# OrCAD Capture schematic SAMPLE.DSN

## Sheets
1 PAGE1: size C; title: Sample Design; rev: A; company: EMA Design Automation; note: 1234567890; note: 225 Tech Park Dr.; note: Rochester, NY 14623
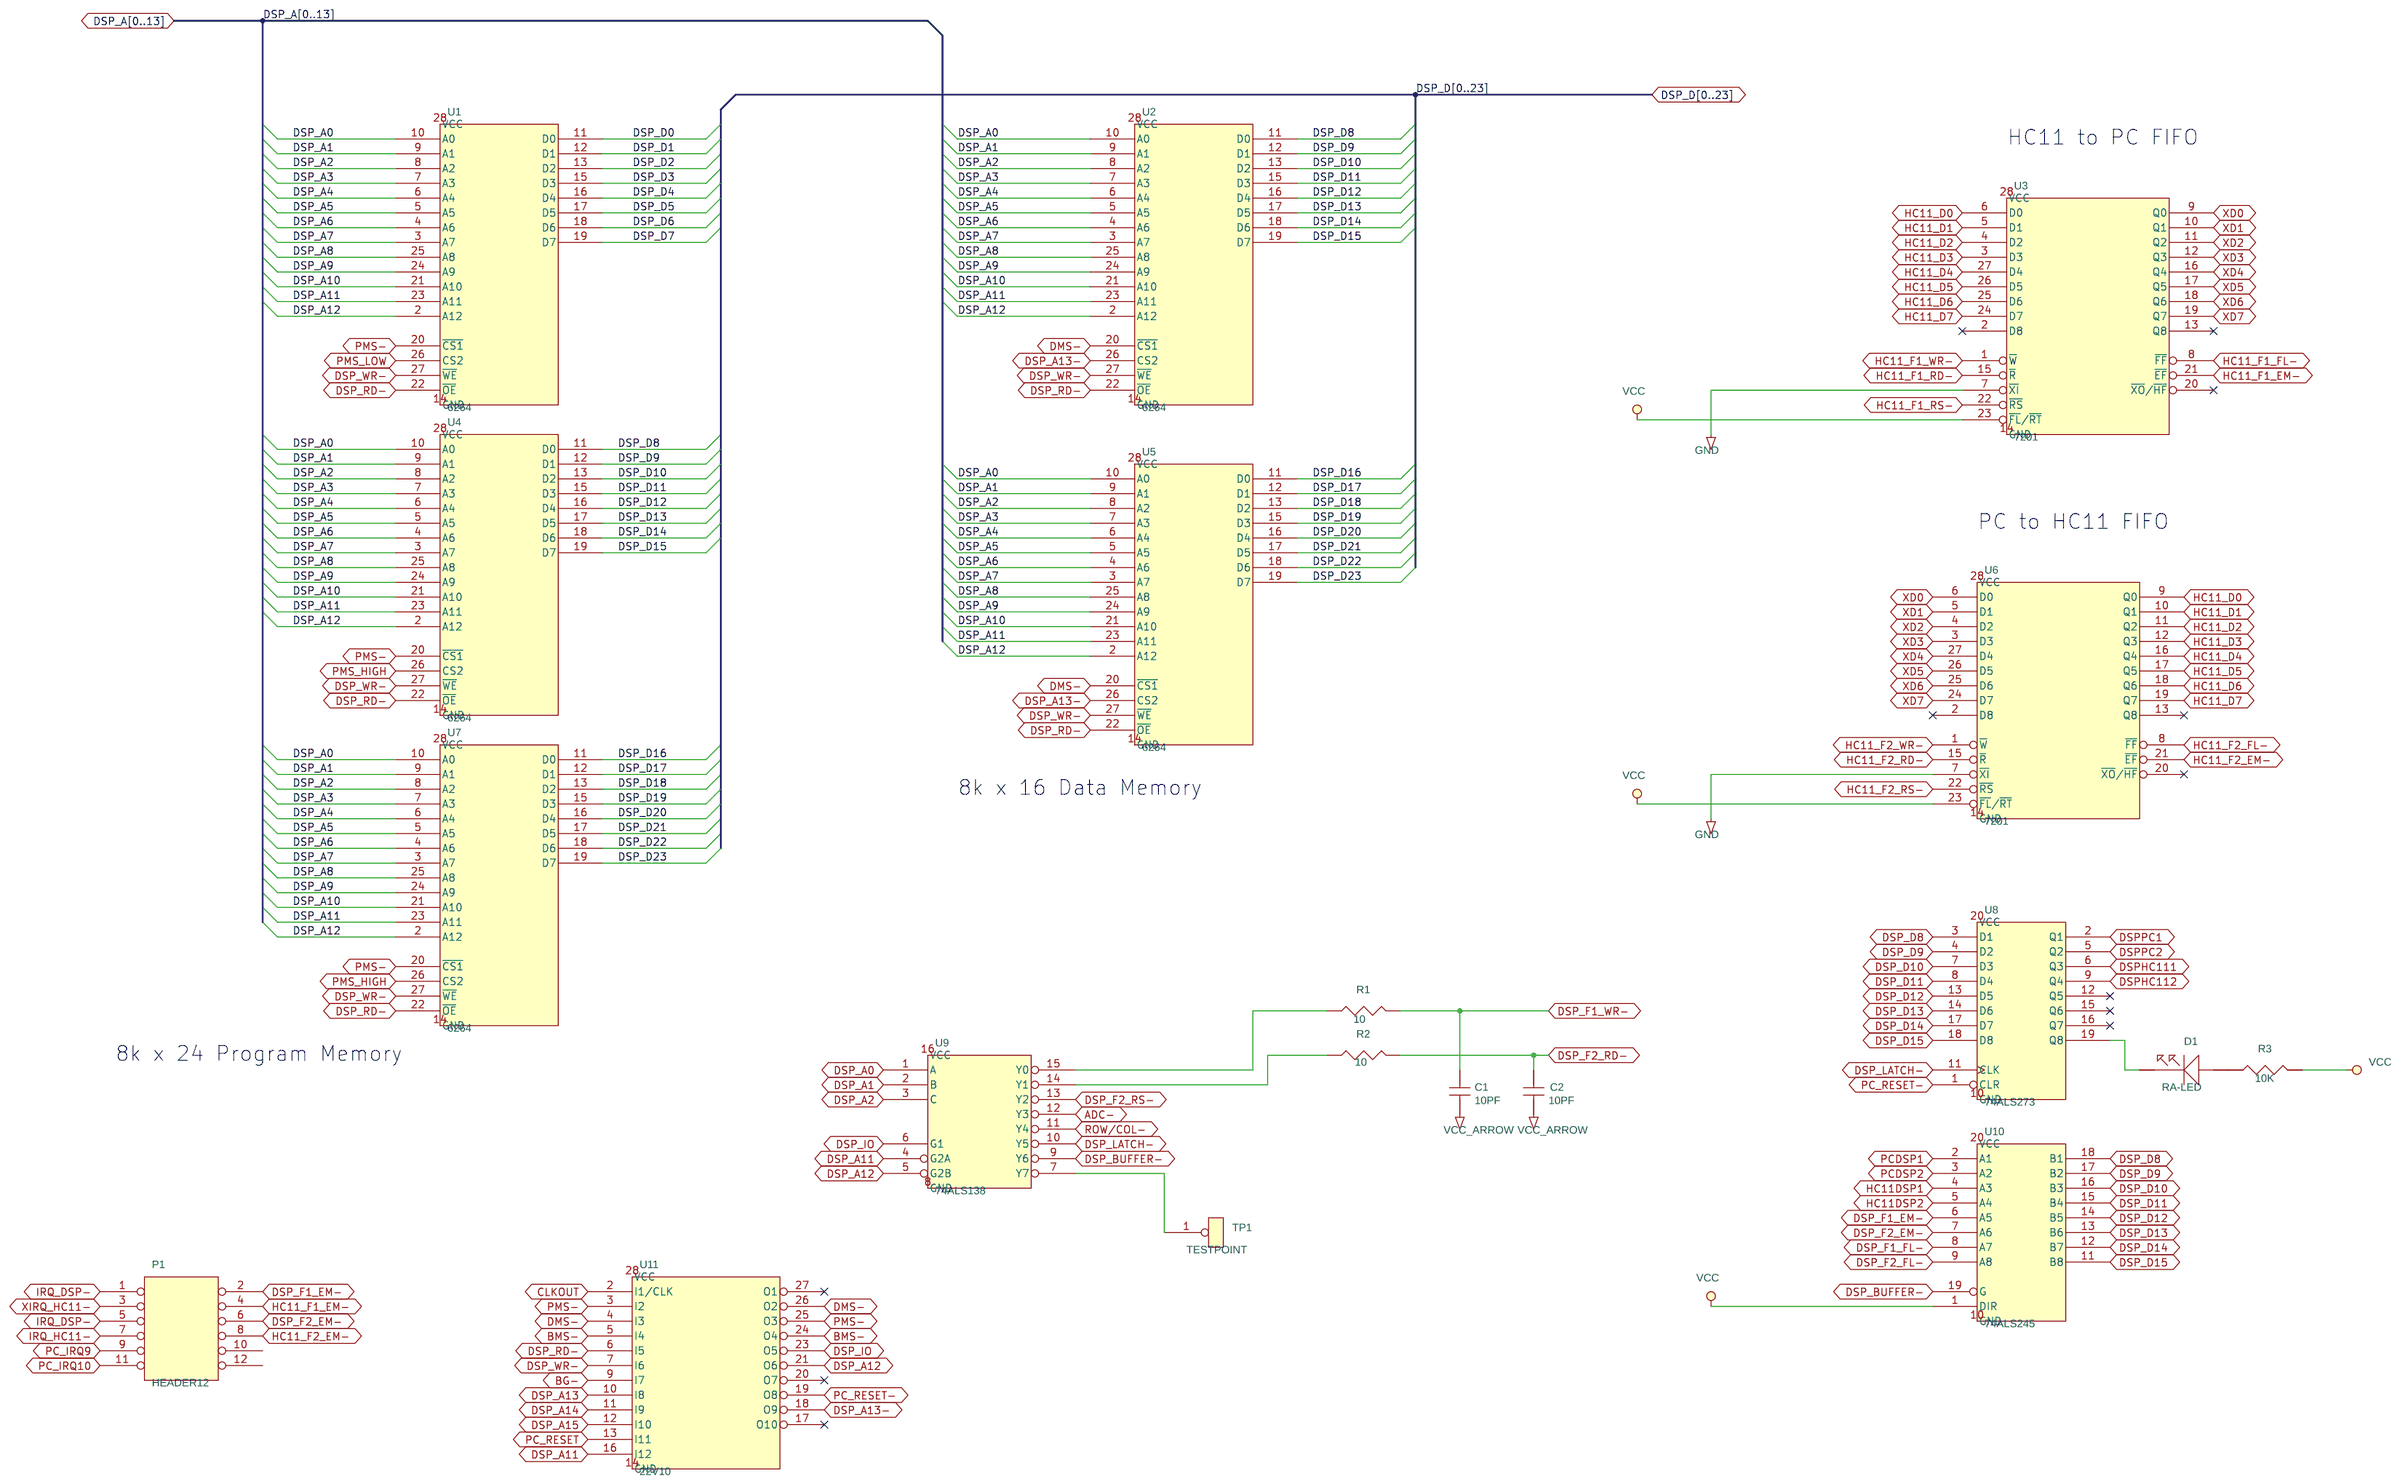
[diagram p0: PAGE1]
2 PAGE2: size C
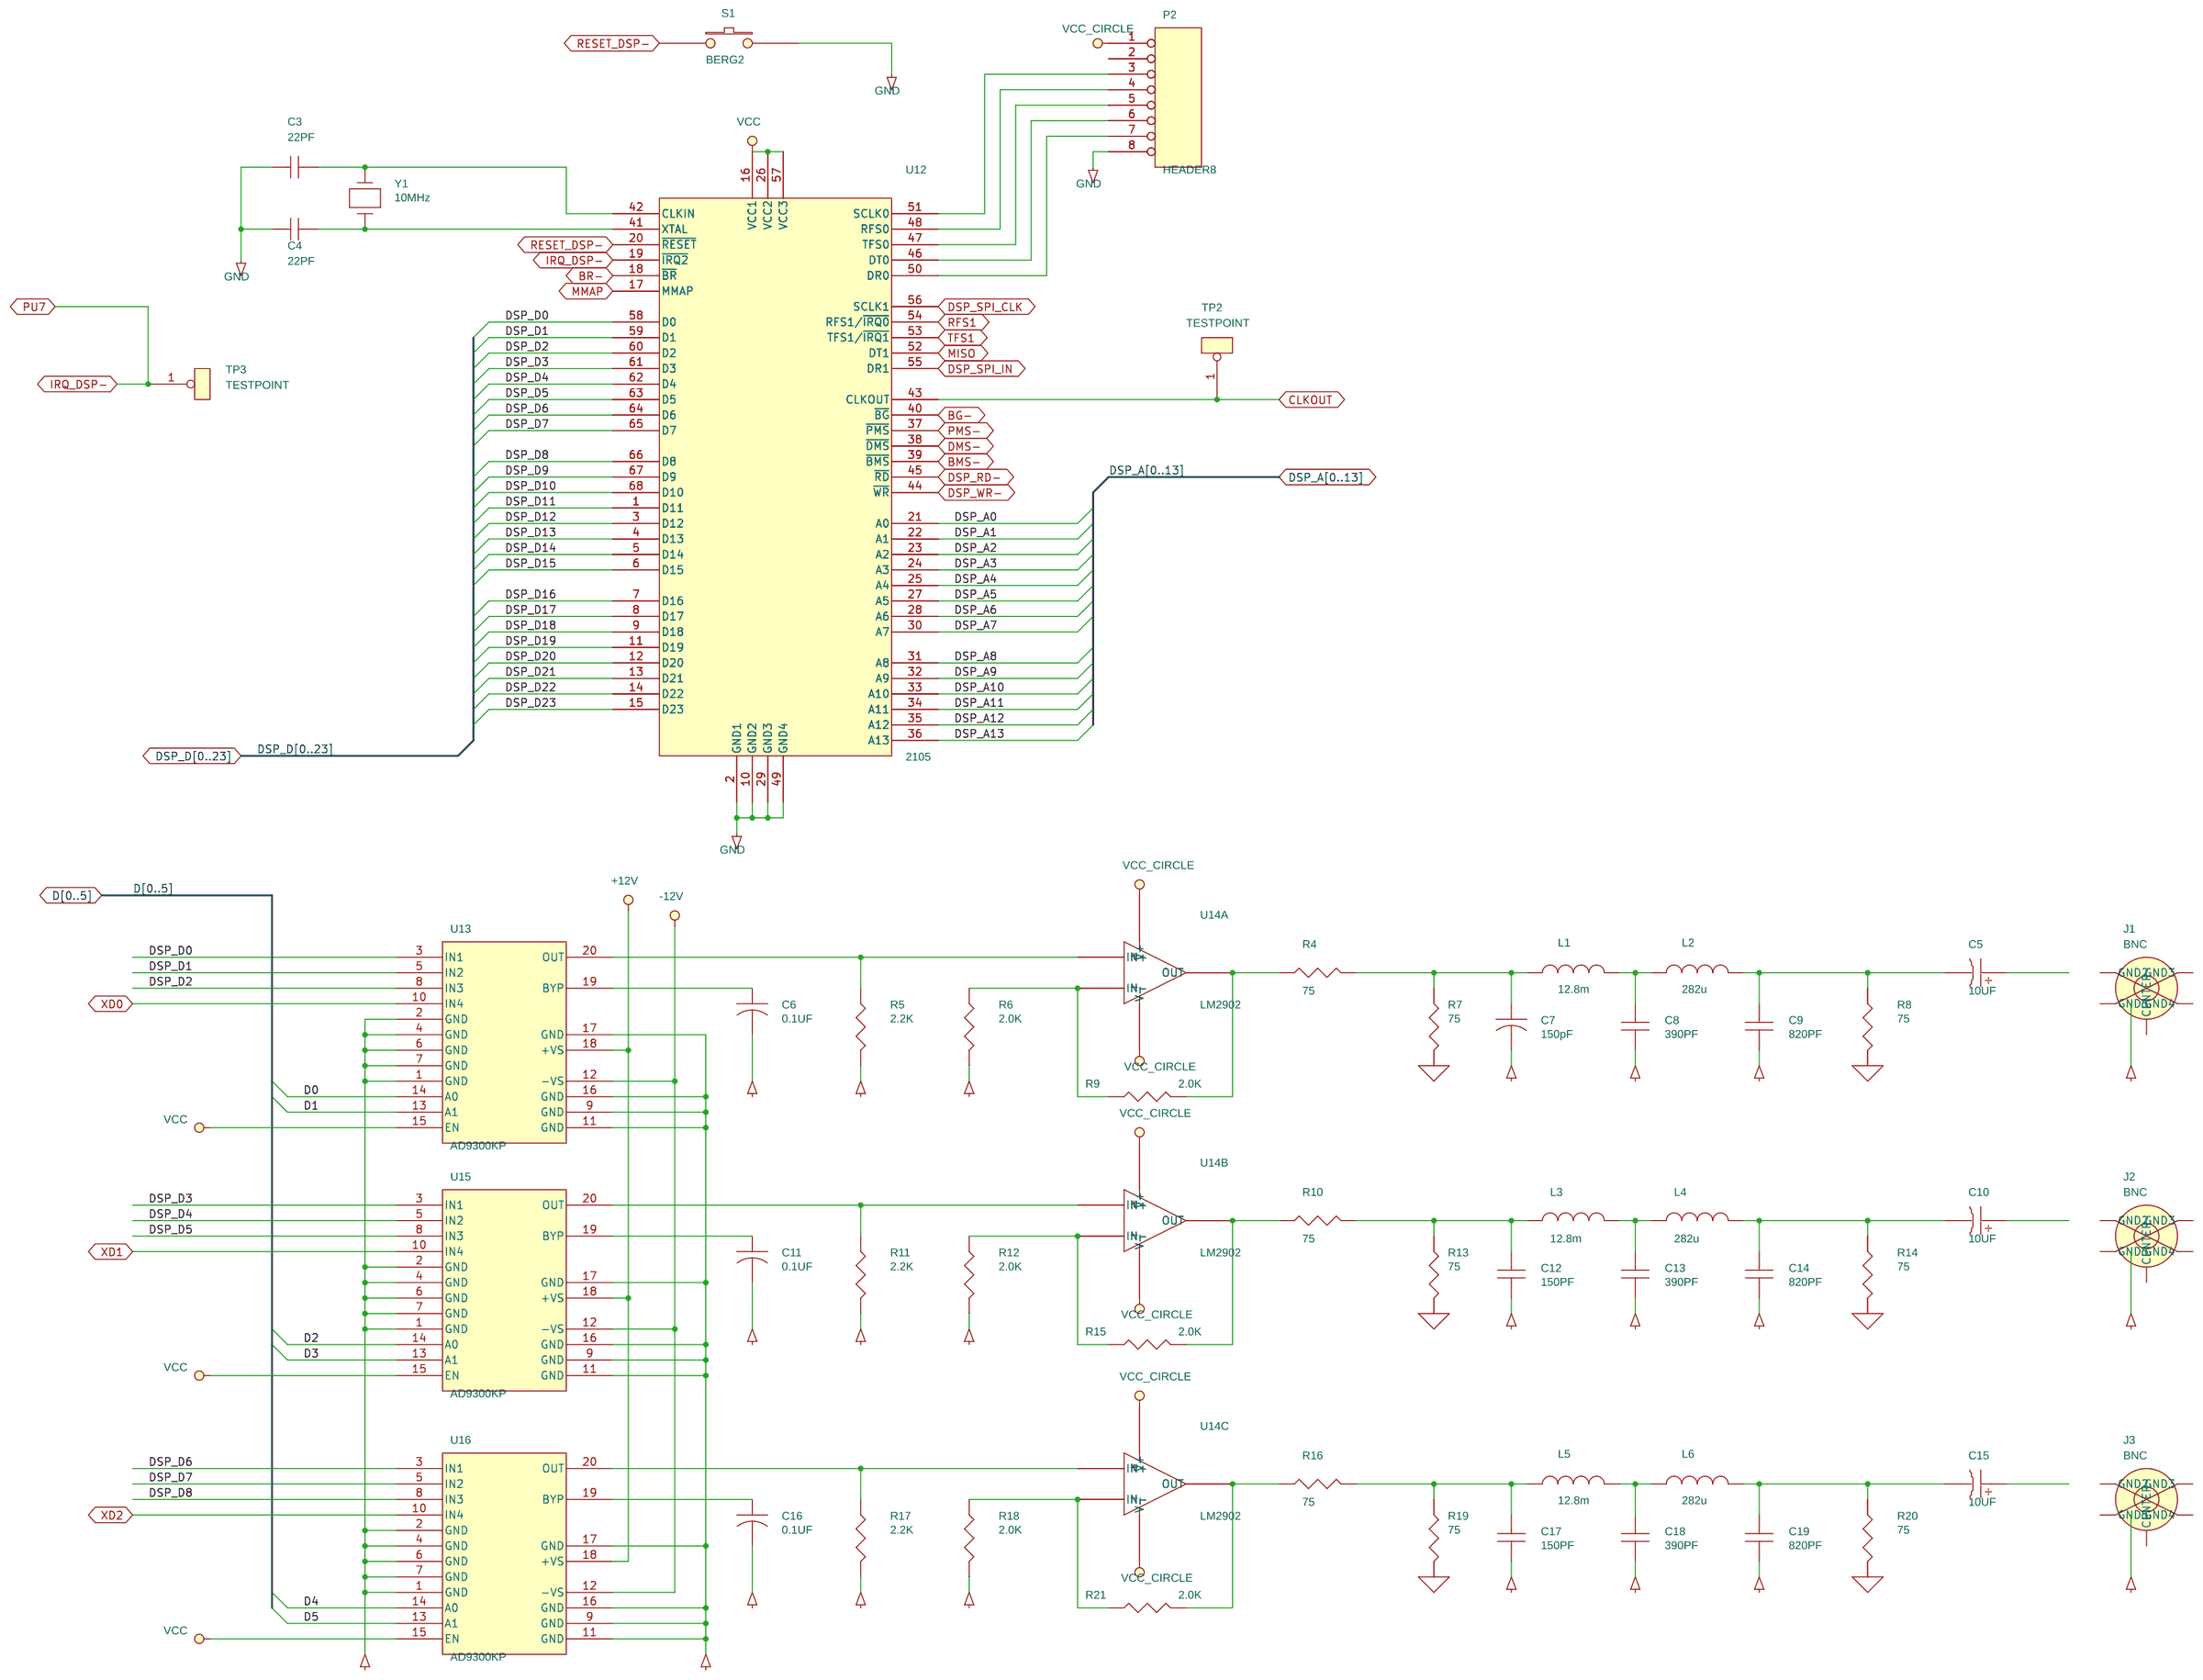
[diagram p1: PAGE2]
3 PAGE3: size C
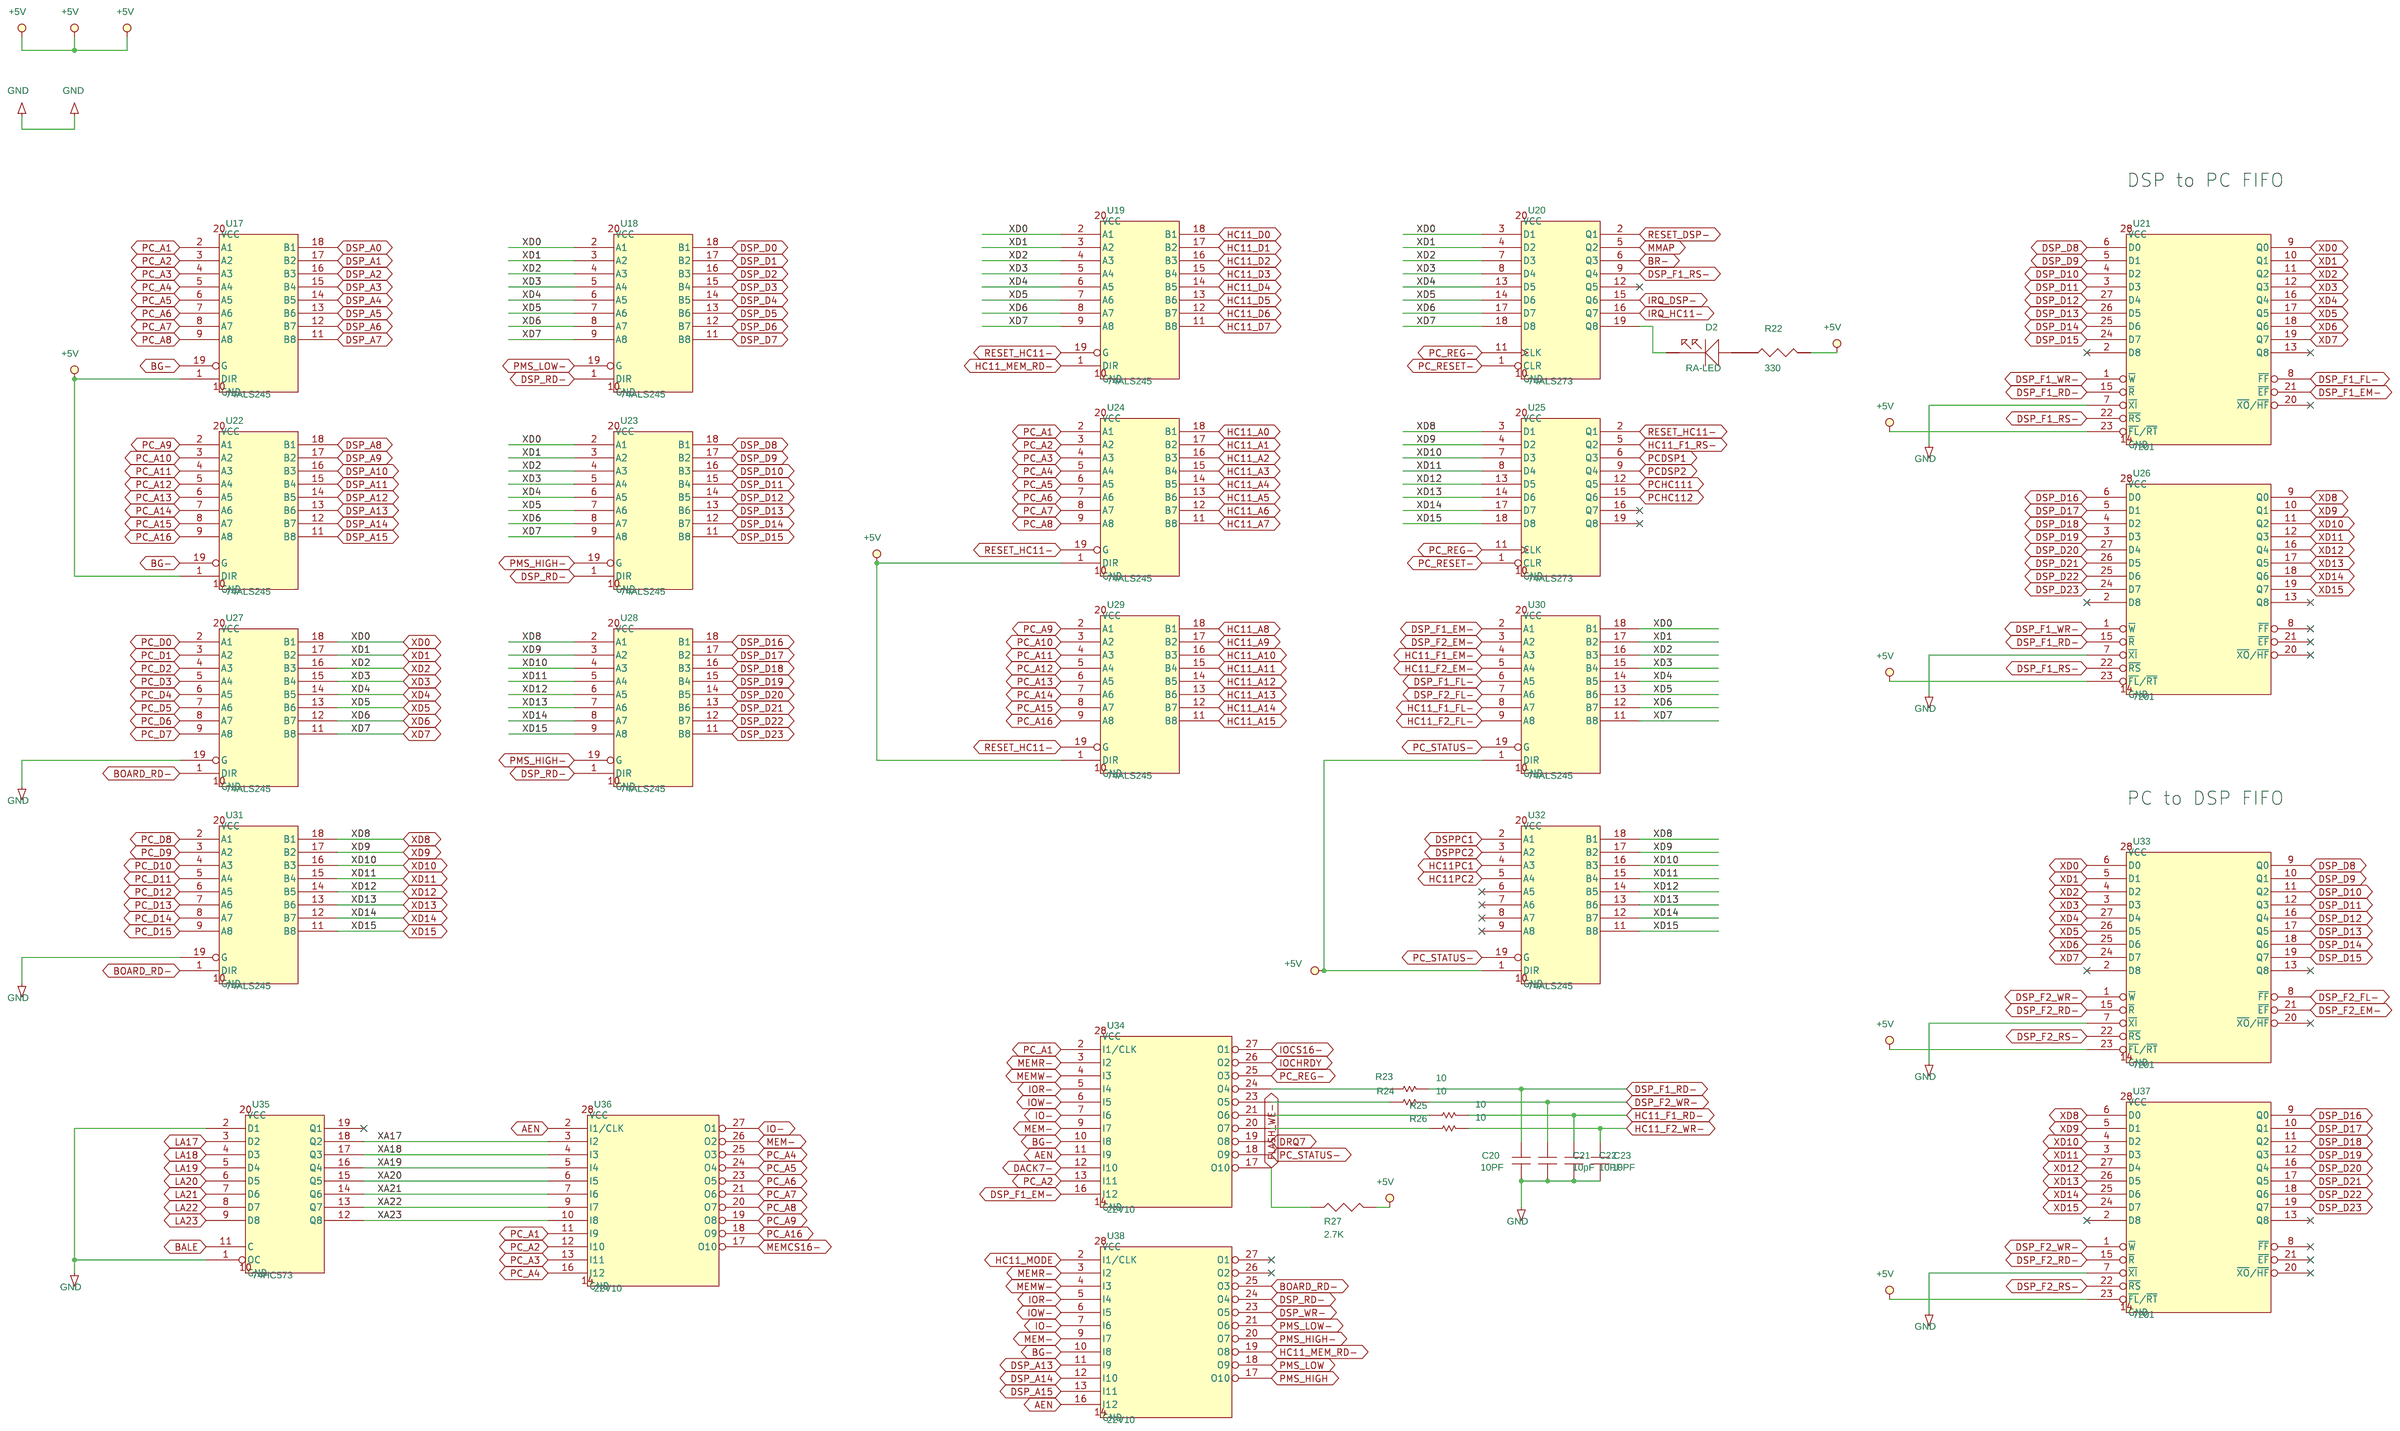
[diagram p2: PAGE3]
4 PAGE4: size C
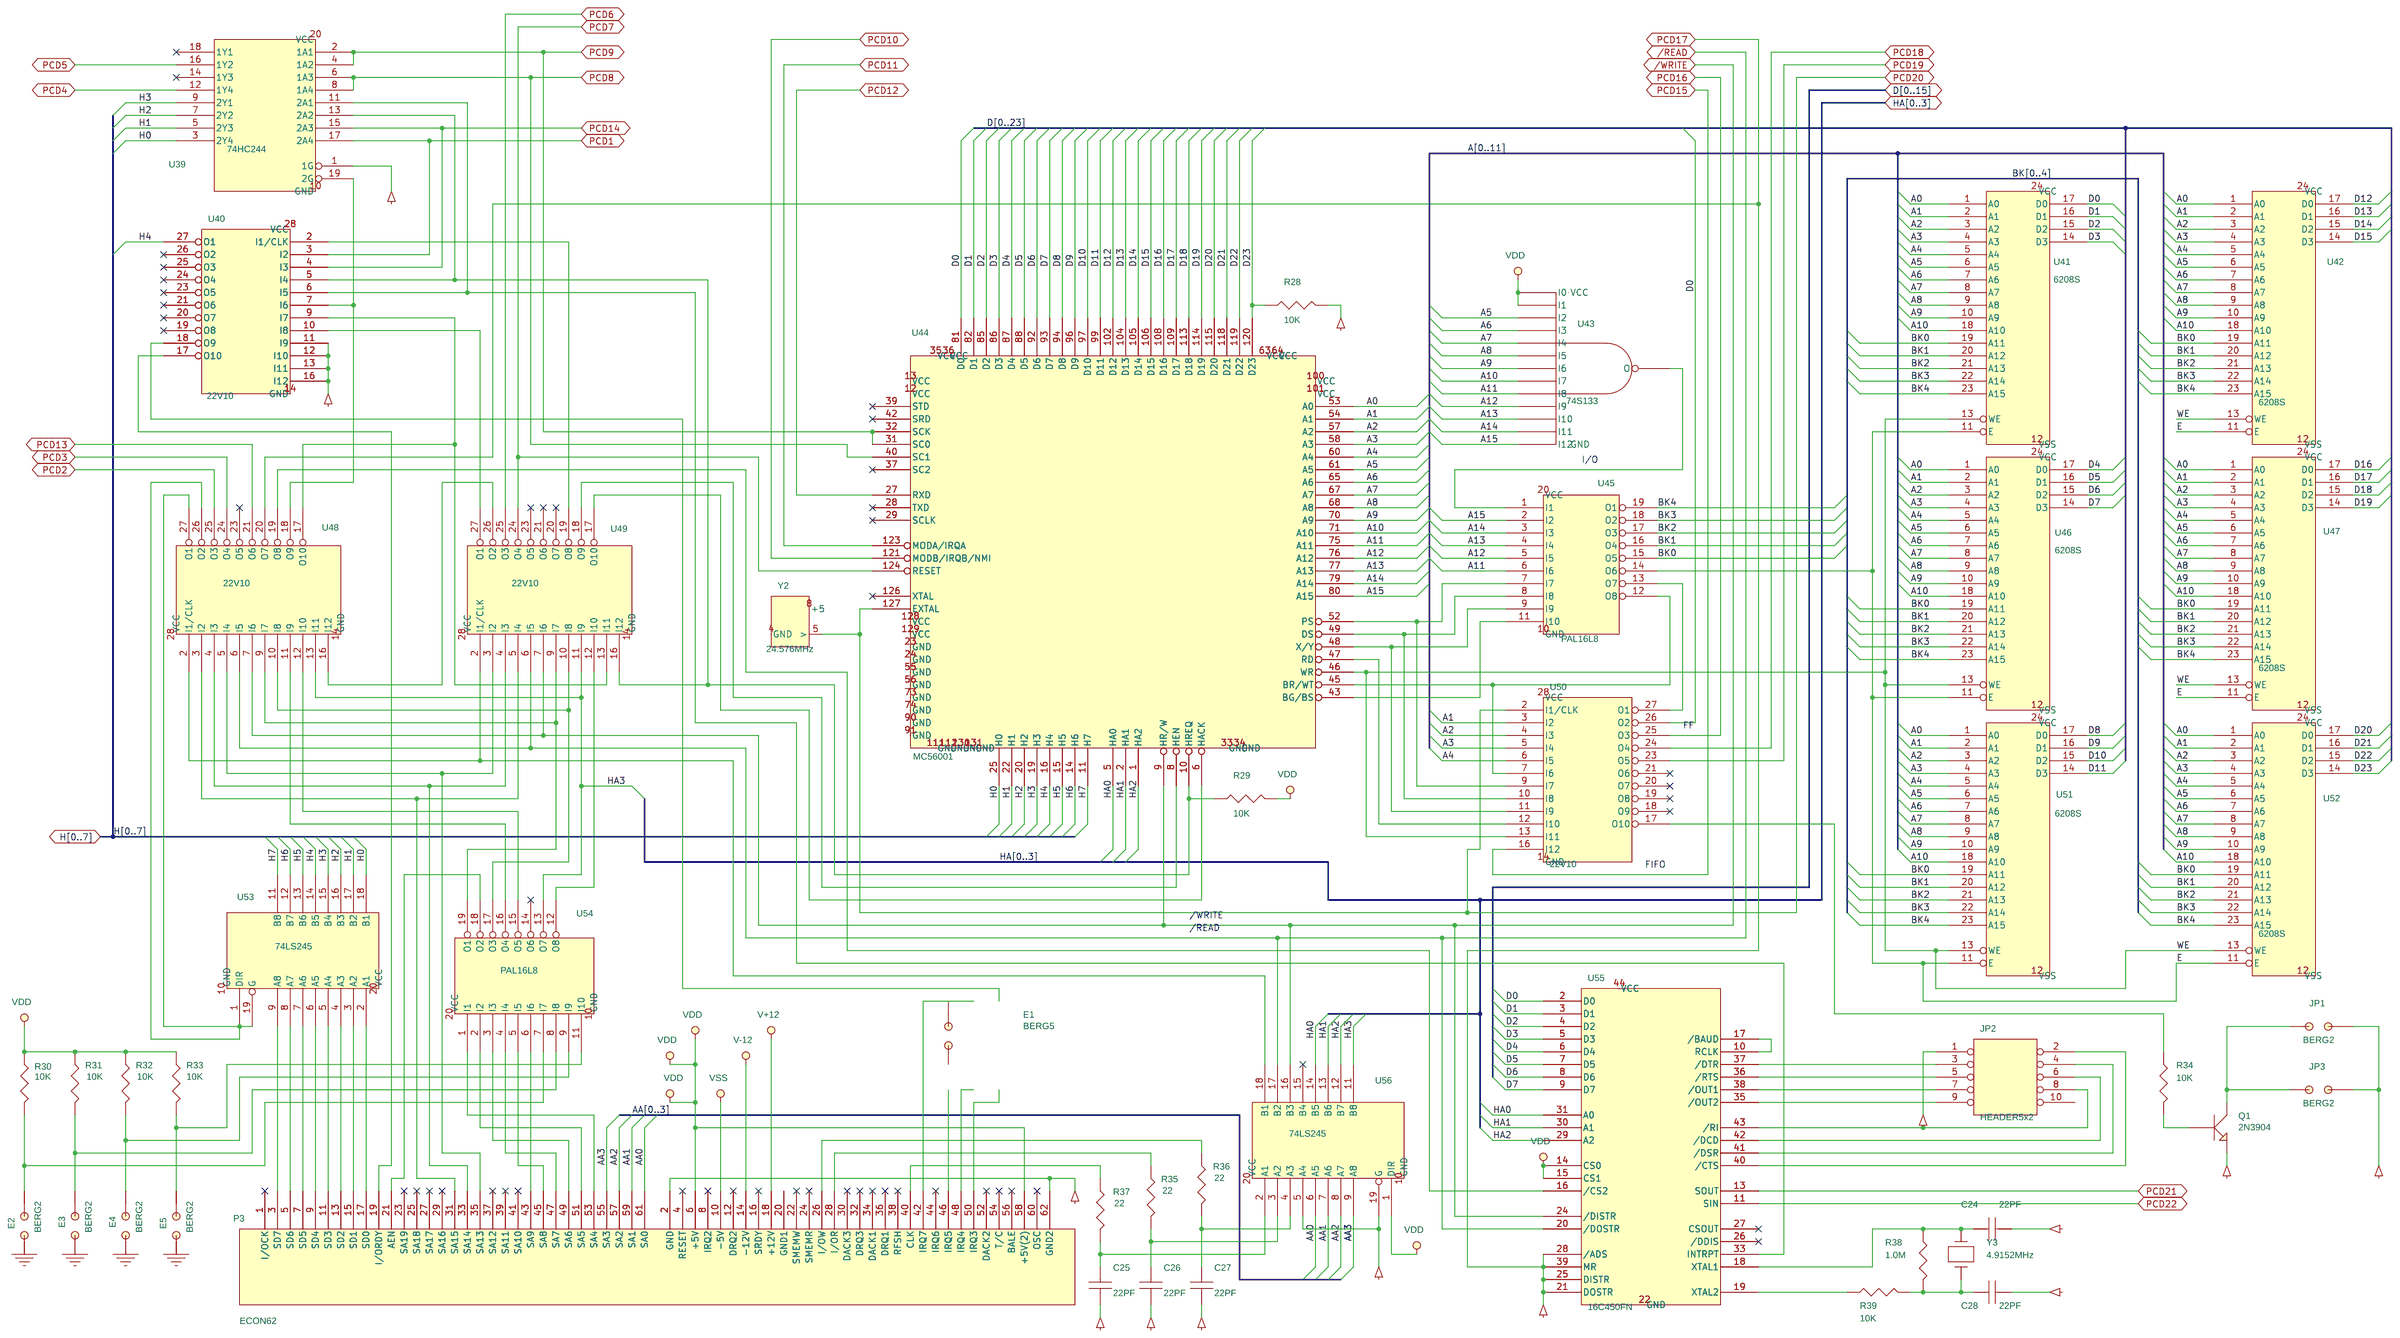
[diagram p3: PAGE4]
5 PAGE5: size C; note: Rochester, NY
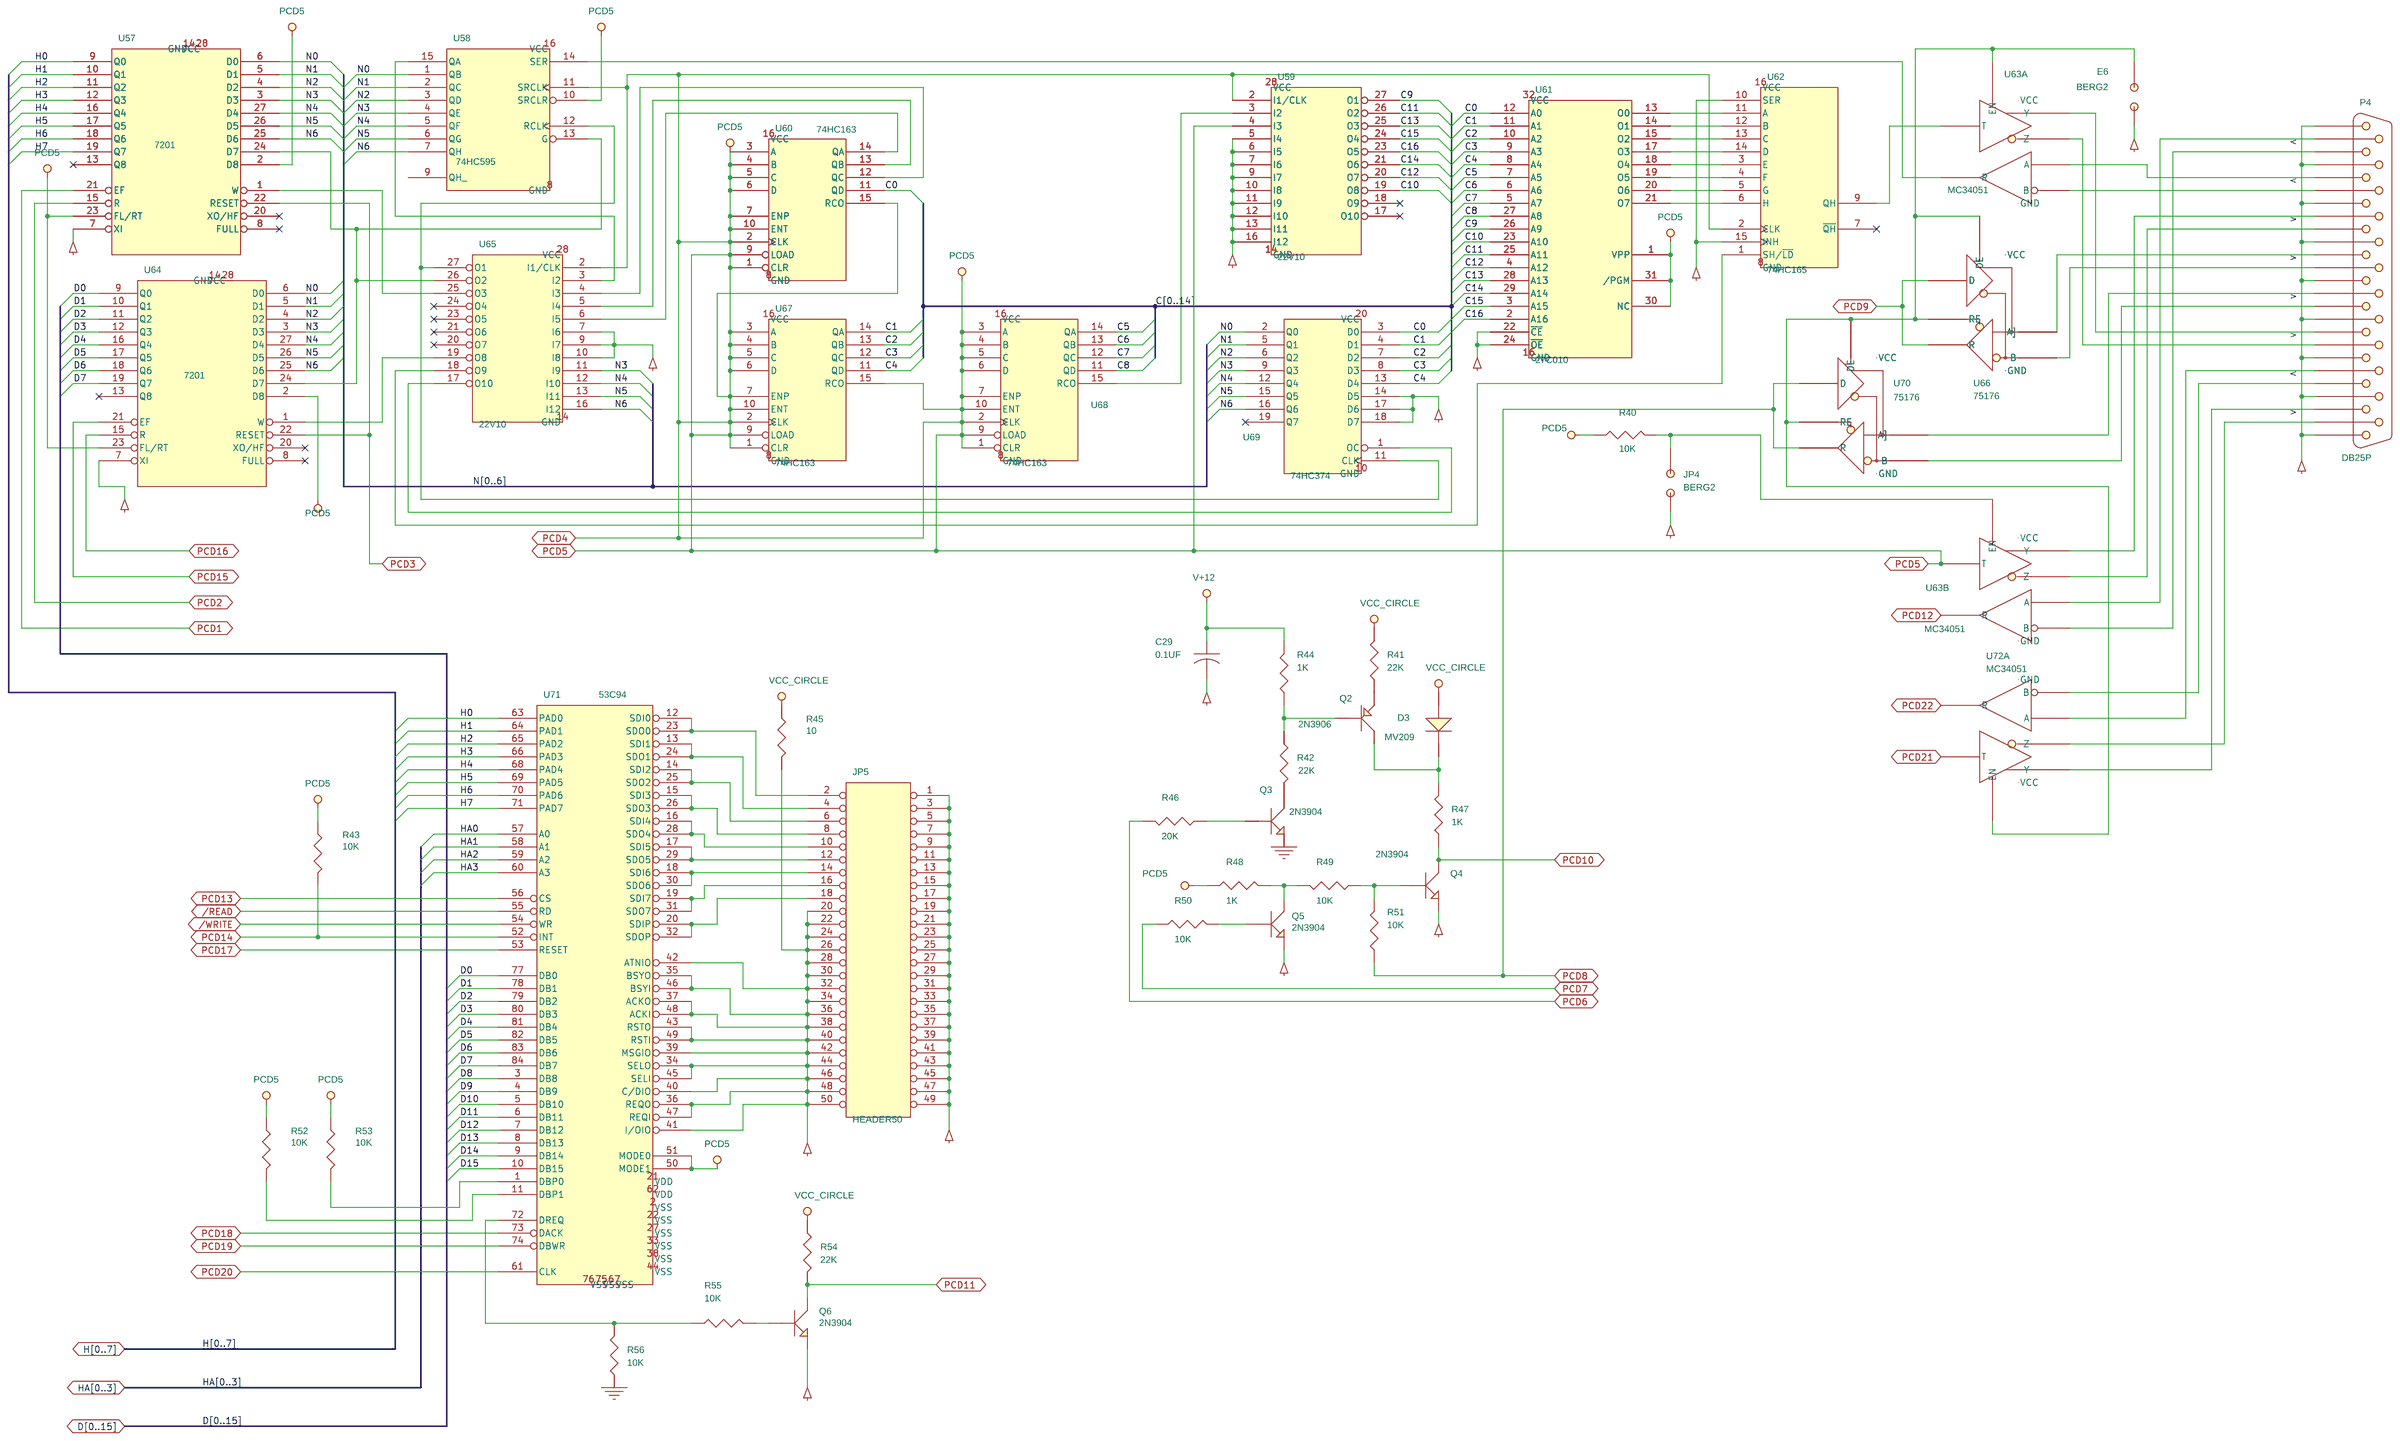
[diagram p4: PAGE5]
6 PAGE6: size C; note: Rochester, NY
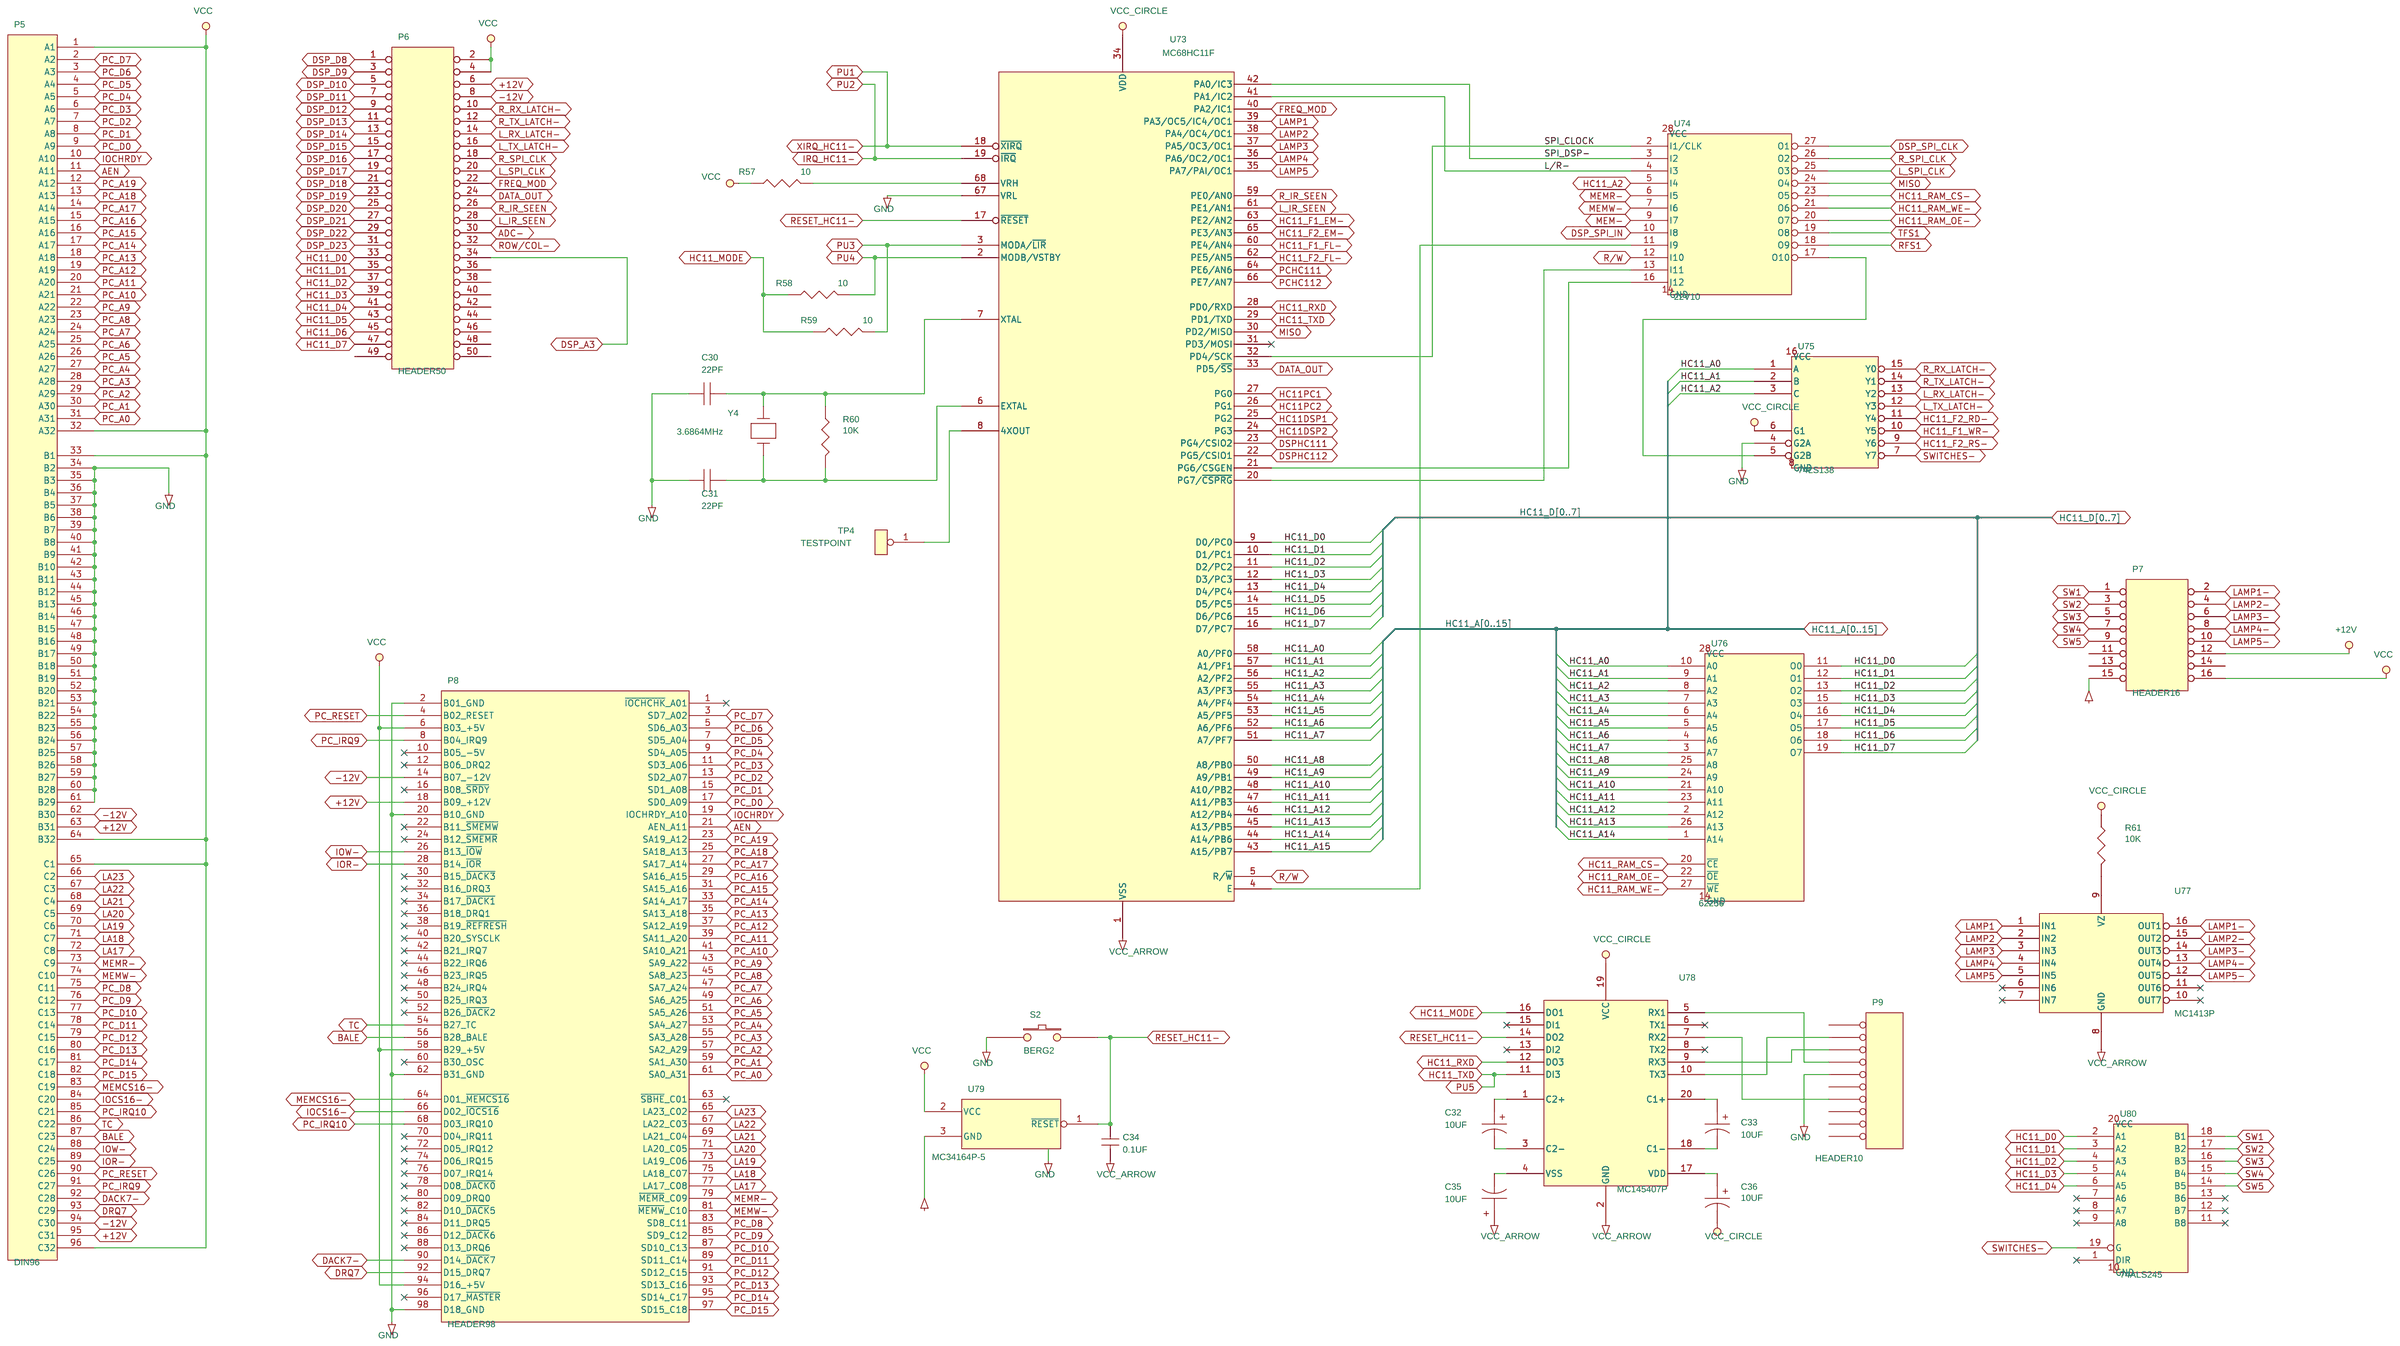
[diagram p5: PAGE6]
7 PAGE7: size B; note: Rochester, NY
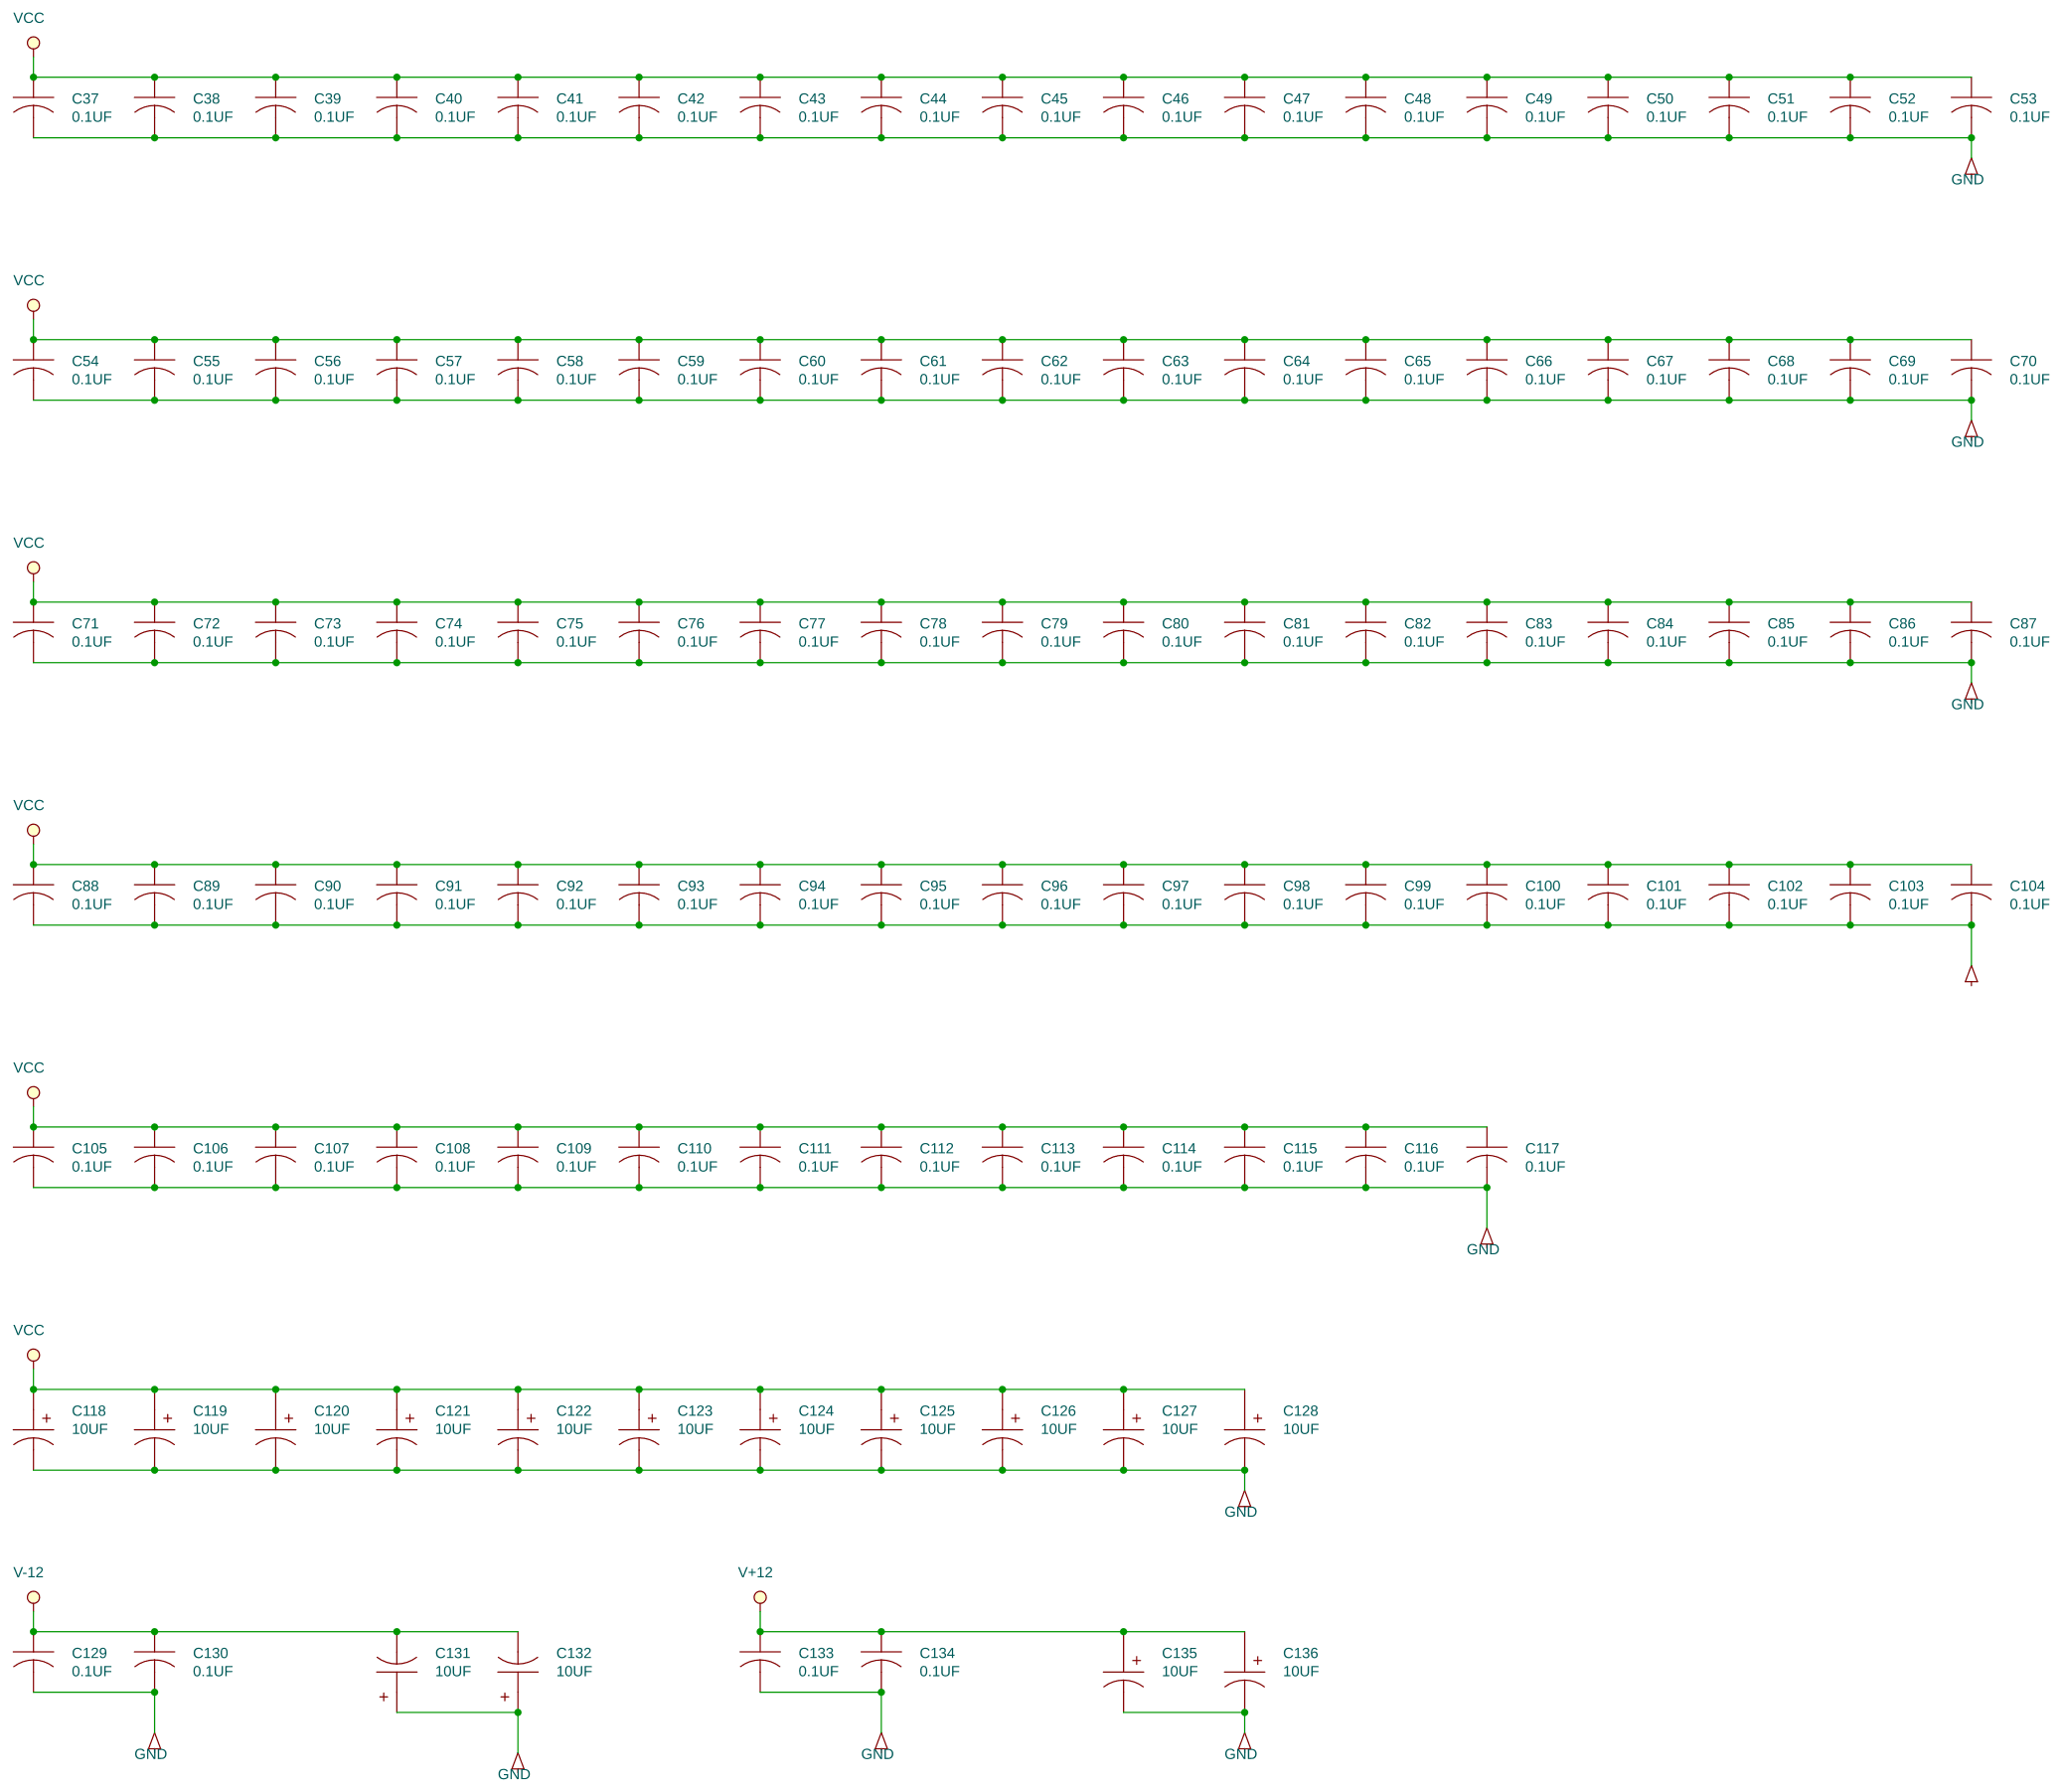
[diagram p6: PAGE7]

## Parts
sheet PAGE1
C1  10PF  [SM/C_0402]
C2  10PF  [SM/C_0402]
D1  RA-LED  [DAX2/.450X.090/.031]
P1  HEADER12  [BLKCON.100/VH/TM1SQS/W.100/12]
R1  10  [SM/R_0603]
R2  10  [SM/R_0603]
R3  10K  [AX/RC05]
TP1  TESTPOINT  [SIP\1P]
U1  6264  [DIP.100/20/W.300/L1.050]
U2  6264  [DIP.100/20/W.300/L1.050]
U3  7201  [DIP.100/16/W.300/L.800]
U4  6264  [DIP.100/20/W.300/L1.050]
U5  6264  [DIP.100/20/W.300/L1.050]
U6  7201  [DIP.100/16/W.300/L.800]
U7  6264  [DIP.100/20/W.300/L1.050]
U8  74ALS273  [DIP.100/20/W.300/L1.050]
U9  74ALS138  [DIP.100/16/W.300/L.775]
U10  74ALS245  [DIP.100/20/W.300/L1.050]
U11  22V10  [PLCC28]
sheet PAGE2
C3  22PF  [SM/C_0805]
C4  22PF  [SM/C_0805]
C5  10UF  [SM/C_0805]
C6  0.1UF  [SM/C_0805]
C7  150pF  [CYL/D.200/LS.100/.031]
C8  390PF  [SM/C_0805]
C9  820PF  [SM/C_0805]
C10  10UF  [SM/C_0805]
C11  0.1UF  [SM/C_1206]
C12  150PF  [SM/C_0805]
C13  390PF  [SM/C_0805]
C14  820PF  [SM/C_0805]
C15  10UF  [SM/C_0805]
C16  0.1UF  [SM/C_1206]
C17  150PF  [SM/C_0805]
C18  390PF  [SM/C_0805]
C19  820PF  [SM/C_0805]
J1  BNC  [BNC]
J2  BNC  [BNC]
J3  BNC  [BNC]
L1  12.8m  [AX/.300X.100/.031]
L2  282u  [AX/.300X.100/.031]
L3  12.8m  [AX/.300X.100/.031]
L4  282u  [AX/.300X.100/.031]
L5  12.8m  [AX/.300X.100/.031]
L6  282u  [AX/.300X.100/.031]
P2  HEADER8  [SIP/TM/L.800/8]
R4  75  [SM/R_1206]
R5  2.2K  [SM/R_1206]
R6  2.0K  [SM/R_0805]
R7  75  [SM/R_1206]
R8  75  [SM/R_1206]
R9  2.0K  [SM/R_1206]
R10  75  [SM/R_1206]
R11  2.2K  [SM/R_1206]
R12  2.0K  [SM/R_0805]
R13  75  [SM/R_1206]
R14  75  [SM/R_1206]
R15  2.0K  [SM/R_1206]
R16  75  [SM/R_1206]
R17  2.2K  [SM/R_1206]
R18  2.0K  [SM/R_1206]
R19  75  [SM/R_1206]
R20  75  [SM/R_1206]
R21  2.0K  [SM/R_0805]
S1  BERG2  [JUMPER\JUMPER200]
TP2  TESTPOINT  [SIP\1P]
TP3  TESTPOINT  [SIP\1P]
U12  2105  [DIP.100/20/W.300/L1.050]
U13  AD9300KP  [PLCC20]
U14  LM2902  [DIP.100/14/W.300/L.800]  (sections A,B,C)
U15  AD9300KP  [PLCC20]
U16  AD9300KP  [PLCC20]
Y1  10MHz  [DISC/.350X.175/LS.200X.050/.034]
sheet PAGE3
C20  10PF  [SM/C_0402]
C21  10pF  [SM/C_0402]
C22  10PF  [SM/C_0402]
C23  10PF  [SM/C_0402]
D2  RA-LED  [DAX2/.450X.090/.031]
R22  330  [SM/R_0805]
R23  10  [SM/R_0402]
R24  10  [SM/R_0402]
R25  10  [SM/R_0402]
R26  10  [SM/R_0402]
R27  2.7K  [SM/R_0402]
U17  74ALS245  [DIP.100/20/W.300/L1.050]
U18  74ALS245  [DIP.100/20/W.300/L1.050]
U19  74ALS245  [DIP.100/20/W.300/L1.050]
U20  74ALS273  [DIP.100/20/W.300/L1.050]
U21  7201  [DIP.100/16/W.300/L.800]
U22  74ALS245  [DIP.100/20/W.300/L1.050]
U23  74ALS245  [DIP.100/20/W.300/L1.050]
U24  74ALS245  [DIP.100/20/W.300/L1.050]
U25  74ALS273  [DIP.100/20/W.300/L1.050]
U26  7201  [DIP.100/16/W.300/L.800]
U27  74ALS245  [DIP.100/20/W.300/L1.050]
U28  74ALS245  [DIP.100/20/W.300/L1.050]
U29  74ALS245  [DIP.100/20/W.300/L1.050]
U30  74ALS245  [DIP.100/20/W.300/L1.050]
U31  74ALS245  [DIP.100/20/W.300/L1.050]
U32  74ALS245  [DIP.100/20/W.300/L1.050]
U33  7201  [DIP.100/16/W.300/L.800]
U34  22V10  [PLCC28]
U35  74HC573  [DIP.100/20/W.300/L1.050]
U36  22V10  [PLCC28]
U37  7201  [DIP.100/16/W.300/L.800]
U38  22V10  [PLCC28]
sheet PAGE4
C24  22PF  [SM/C_0805]
C25  22PF  [SM/C_0805]
C26  22PF  [SM/C_0805]
C27  22PF  [SM/C_0805]
C28  22PF  [SM/C_0805]
E1  BERG5  [jumper5]
E2  BERG2  [JUMPER\JUMPER200]
E3  BERG2  [JUMPER\JUMPER200]
E4  BERG2  [JUMPER\JUMPER200]
E5  BERG2  [JUMPER\JUMPER200]
JP1  BERG2  [JUMPER\JUMPER200]
JP2  HEADER5x2  [LATCON.100/VH/TM2OE/W.350/10]
JP3  BERG2  [JUMPER\JUMPER200]
P3  ECON62  [ECON.100/VS/TM2SQ/W.400/62]
Q1  2N3904  [TO220AB]
R28  10K  [AX/RC05]
R29  10K  [AX/RC05]
R30  10K  [AX/RC05]
R31  10K  [AX/RC05]
R32  10K  [AX/RC05]
R33  10K  [AX/RC05]
R34  10K  [AX/RC05]
R35  22  [SM/R_0805]
R36  22  [SM/R_0805]
R37  22  [SM/R_0805]
R38  1.0M  [SM/R_1206]
R39  10K  [AX/RC05]
U39  74HC244  [DIP.100/20/W.300/L1.050]
U40  22V10  [PLCC28]
U41  6208S  [DIP.100/18/W.300/L.900]
U42  6208S  [DIP.100/18/W.300/L.900]
U43  74S133  [DIP.100/20/W.300/L1.050]
U44  MC56001  [PGA11_.050/88/D.034/W1.200]
U45  PAL16L8  [DIP.100/20/W.300/L1.050]
U46  6208S  [DIP.100/18/W.300/L.900]
U47  6208S  [DIP.100/18/W.300/L.900]
U48  22V10  [PLCC28]
U49  22V10  [PLCC28]
U50  22V10  [PLCC28]
U51  6208S  [DIP.100/18/W.300/L.900]
U52  6208S  [DIP.100/18/W.300/L.900]
U53  74LS245  [DIP.100/20/W.300/L1.050]
U54  PAL16L8  [DIP.100/20/W.300/L1.050]
U55  16C450FN  [QUAD.050/44/WG.785/CTX]
U56  74LS245  [DIP.100/20/W.300/L1.050]
Y2  24.576MHz  [DIP.100/14/W.300/L.800]
Y3  4.9152MHz  [DISC/.350X.175/LS.200X.050/.034]
sheet PAGE5
C29  0.1UF  [SM/C_1206]
D3  MV209  [T0220AC]
E6  BERG2  [JUMPER\JUMPER200]
JP4  BERG2  [JUMPER\JUMPER200]
JP5  HEADER50  [LATCON.100/VH/TM2OE/W.350/50]
P4  DB25P  [DSUB/VP/TM/25]
Q2  2N3906  [TO220AB]
Q3  2N3904  [TO220AB]
Q4  2N3904  [TO220AB]
Q5  2N3904  [TO220AB]
Q6  2N3904  [TO220AB]
R40  10K  [AX/RC05]
R41  22K  [SM/R_0805]
R42  22K  [SM/R_0805]
R43  10K  [AX/RC05]
R44  1K  [SM/R_1206]
R45  10  [SM/R_0805]
R46  20K  [SM/R_1206]
R47  1K  [SM/R_1206]
R48  1K  [SM/R_1206]
R49  10K  [AX/RC05]
R50  10K  [AX/RC05]
R51  10K  [AX/RC05]
R52  10K  [AX/RC05]
R53  10K  [AX/RC05]
R54  22K  [SM/R_0805]
R55  10K  [SM/R_0805]
R56  10K  [AX/RC05]
U57  7201  [DIP.100/16/W.300/L.800]
U58  74HC595  [DIP.100/20/W.300/L1.050]
U59  22V10  [PLCC28]
U60  74HC163  [DIP.100/20/W.300/L1.050]
U61  27C010  [PLCC32]
U62  74HC165  [DIP.100/20/W.300/L1.050]
U63  MC34051  [SOJ.050/16/WB.300/L.400]  (sections A,B)
U64  7201  [DIP.100/16/W.300/L.800]
U65  22V10  [PLCC28]
U66  75176  [DIP.100/8/W.300/L.400]
U67  74HC163  [DIP.100/20/W.300/L1.050]
U68  74HC163  [DIP.100/20/W.300/L1.050]
U69  74HC374  [DIP.100/20/W.300/L1.050]
U70  75176  [DIP.100/8/W.300/L.400]
U71  53C94  [DIP.100/20/W.300/L1.050]
U72  MC34051  [SOJ.050/16/WB.300/L.400]  (section A)
sheet PAGE6
C30  22PF  [SM/C_0805]
C31  22PF  [SM/C_0805]
C32  10UF  [SM/C_0805]
C33  10UF  [SM/C_0805]
C34  0.1UF  [SM/C_0805]
C35  10UF  [SM/C_0805]
C36  10UF  [SM/C_0805]
P5  DIN96  [DIN96_ABC/R]
P6  HEADER50  [LATCON.100/VH/TM2OE/W.350/50]
P7  HEADER16  [LATCON.100/VH/TM2OE/W.350/16]
P8  HEADER98  [BLKCON.100/VH/TM20E/W.200/96]
P9  HEADER10  [LATCON.100/VH/TM2OE/W.350/10]
R57  10  [SM/R_0603]
R58  10  [SM/R_0603]
R59  10  [SM/R_0603]
R60  10K  [AX/RC05]
R61  10K  [AX/RC05]
S2  BERG2  [JUMPER\JUMPER200]
TP4  TESTPOINT  [SIP\1P]
U73  MC68HC11F  [QUAD.65M/64/WG14.00]
U74  22V10  [PLCC28]
U75  74LS138  [SOJ.050/16/WB.300/L.400]
U76  62256  [DIP.100/16/W.300/L.800]
U77  MC1413P  [DIP.100/16/W.300/L.875]
U78  MC145407P  [DIP.100/20/W.300/L1.050]
U79  MC34164P-5  [TO226AB]
U80  74ALS245  [DIP.100/20/W.300/L1.050]
Y4  3.6864MHz  [DISC/.350X.175/LS.200X.050/.034]
sheet PAGE7
C37  0.1UF  [SM/C_1206]
C38  0.1UF  [SM/C_1206]
C39  0.1UF  [SM/C_1206]
C40  0.1UF  [SM/C_1206]
C41  0.1UF  [SM/C_1206]
C42  0.1UF  [SM/C_1206]
C43  0.1UF  [SM/C_1206]
C44  0.1UF  [SM/C_1206]
C45  0.1UF  [SM/C_1206]
C46  0.1UF  [SM/C_1206]
C47  0.1UF  [SM/C_1206]
C48  0.1UF  [SM/C_1206]
C49  0.1UF  [SM/C_1206]
C50  0.1UF  [SM/C_1206]
C51  0.1UF  [SM/C_1206]
C52  0.1UF  [SM/C_1206]
C53  0.1UF  [SM/C_1206]
C54  0.1UF  [SM/C_1206]
C55  0.1UF  [SM/C_1206]
C56  0.1UF  [SM/C_1206]
C57  0.1UF  [SM/C_1206]
C58  0.1UF  [SM/C_1206]
C59  0.1UF  [SM/C_1206]
C60  0.1UF  [SM/C_1206]
C61  0.1UF  [SM/C_1206]
C62  0.1UF  [SM/C_1206]
C63  0.1UF  [SM/C_1206]
C64  0.1UF  [SM/C_1206]
C65  0.1UF  [SM/C_1206]
C66  0.1UF  [SM/C_1206]
C67  0.1UF  [SM/C_1206]
C68  0.1UF  [SM/C_1206]
C69  0.1UF  [SM/C_1206]
C70  0.1UF  [SM/C_1206]
C71  0.1UF  [SM/C_1206]
C72  0.1UF  [SM/C_1206]
C73  0.1UF  [SM/C_1206]
C74  0.1UF  [SM/C_1206]
C75  0.1UF  [SM/C_1206]
C76  0.1UF  [SM/C_1206]
C77  0.1UF  [SM/C_1206]
C78  0.1UF  [SM/C_1206]
C79  0.1UF  [SM/C_1206]
C80  0.1UF  [SM/C_1206]
C81  0.1UF  [SM/C_1206]
C82  0.1UF  [SM/C_1206]
C83  0.1UF  [SM/C_1206]
C84  0.1UF  [SM/C_1206]
C85  0.1UF  [SM/C_1206]
C86  0.1UF  [SM/C_1206]
C87  0.1UF  [SM/C_1206]
C88  0.1UF  [SM/C_1206]
C89  0.1UF  [SM/C_1206]
C90  0.1UF  [SM/C_1206]
C91  0.1UF  [SM/C_1206]
C92  0.1UF  [SM/C_1206]
C93  0.1UF  [SM/C_1206]
C94  0.1UF  [SM/C_1206]
C95  0.1UF  [SM/C_1206]
C96  0.1UF  [SM/C_1206]
C97  0.1UF  [SM/C_1206]
C98  0.1UF  [SM/C_1206]
C99  0.1UF  [SM/C_1206]
C100  0.1UF  [SM/C_1206]
C101  0.1UF  [SM/C_1206]
C102  0.1UF  [SM/C_1206]
C103  0.1UF  [SM/C_1206]
C104  0.1UF  [SM/C_1206]
C105  0.1UF  [SM/C_1206]
C106  0.1UF  [SM/C_1206]
C107  0.1UF  [SM/C_1206]
C108  0.1UF  [SM/C_1206]
C109  0.1UF  [SM/C_1206]
C110  0.1UF  [SM/C_1206]
C111  0.1UF  [SM/C_1206]
C112  0.1UF  [SM/C_1206]
C113  0.1UF  [SM/C_1206]
C114  0.1UF  [SM/C_1206]
C115  0.1UF  [SM/C_1206]
C116  0.1UF  [SM/C_1206]
C117  0.1UF  [SM/C_1206]
C118  10UF  [CP2412]
C119  10UF  [CP2412]
C120  10UF  [CP2412]
C121  10UF  [CP2412]
C122  10UF  [CP2412]
C123  10UF  [CP2412]
C124  10UF  [CP2412]
C125  10UF  [CP2412]
C126  10UF  [CP2412]
C127  10UF  [CP2412]
C128  10UF  [CP2412]
C129  0.1UF  [SM/C_1206]
C130  0.1UF  [SM/C_1206]
C131  10UF  [CP2412]
C132  10UF  [CP2412]
C133  0.1UF  [SM/C_1206]
C134  0.1UF  [SM/C_1206]
C135  10UF  [CP2412]
C136  10UF  [CP2412]

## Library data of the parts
C1 C2 C20-C23 = SMALL_CAP: PSpice: C; Part Number: PCC100CQTR-ND; Voltage: 50V
D1 D2 = LED1: PSpice: D; Part Number: 40-00017; Rating: 2.0V
P1 = HEADER_6X2: Part Number: 60-00037
R1 R2 R57-R59 = RESISTOR: PSpice: R; Part Number: ERJ-3GSYJ100V; Power: 1/16W; Tolerance: 5%
R3 R28 R61 = RESISTOR: PSpice: R; Part Number: ERJ-8GEYJ103V; Power: 1/8W; Tolerance: 5%
TP1-TP4 = TP-105-01-00: Part Number: 60-00038
U1 U2 U4 U5 U7 = 7C185: Part Number: 20-00062
U3 U6 U21 U26 U33 U37 = IDT7201: Part Number: 20-00042
U8 U20 U25 = 74ALS273: PSpice: 74LS273; Part Number: 20-81432
U9 = 74ALS138: Part Number: TMP-2
U10 U17-U19 U22-U24 U27-U32 U80 = 74ALS245: PSpice: 74LS245; Part Number: 20-003297
U11 U34 U36 U38 U74 = 22V10: Part Number: TMP-1
C3 C4 = SMALL_CAP: PSpice: C; Part Number: PCC220CNTR-ND; Voltage: 50V
C5 C10 C15 = CP: PSpice: C; Part Number: ECE-V1HA100SP; Voltage: 50V
C6 = CAP
C7 = C: Part Number: PCC151CGTR-ND; Tolerance: 10%
C8 C13 C18 = CAPACITOR_NON-POL: PSpice: C; Part Number: PCC391BNTR-ND; Voltage: 50V
C9 C14 C19 = CAP_NP: PSpice: C; Part Number: PCC821CGTR-ND; Voltage: 50V
C11 C39 C43 C44 C46 C62 C67 C82 C90 C92 C98 C107 C130 = CAP: PSpice: C; Part Number: ECE-B1HGE0R1; Voltage: 50V
C12 C17 = CAPACITOR_NON-POL: PSpice: C; Part Number: PCC151CGTR-ND; Voltage: 50V
C16 = CAP: PSpice: C; Part Number: ECE-A50ZR1; Voltage: 50V
J1-J3 = BNC: Part Number: 70-00037
L1 L3 L5 = INDUCTOR: PSpice: L; Part Number: 80-00089; Rating: 1/4W; Tolerance: 5%
L2 L4 L6 = INDUCTOR: PSpice: L; Part Number: 80-00043; Rating: 1/4W; Tolerance: 5%
P2 = 8_HEADER: Part Number: 60-00039
R4 R7 R8 R10 R13 R14 R16 R19 R20 = R: Part Number: ERJ-8GEYJ750V; Power: 1/8W; Tolerance: 5%
R5 R11 R17 = R: Part Number: ERJ-8GEYJ222V; Power: 1/8W; Tolerance: 5%
R6 R12 R21 = R: Part Number: ERJ-6GEYJ202V; Power: 1/10W; Tolerance: 5%
R9 R15 R18 = R: Part Number: ERJ-8GEYJ202V; Power: 1/8W; Tolerance: 5%
S1 S2 = SW_PUSHBUTTON: Part Number: 70-00029
U12 = ADSP-2101KP-50: Part Number: 20-00067
U13 U15 U16 = AD9300KP: Part Number: 20-00911
U14 = LM2902: Part Number: 20-01201
Y1 = CRYSTAL: Part Number: 20-00442
R22 = RESISTOR: PSpice: R; Part Number: ERJ-6GEYJ331V; Power: 1/10W; Tolerance: 5%
R23-R26 = SMALL_R1: PSpice: R; Part Number: ERJ-2GEJ100X; Power: 1/16W; Tolerance: 5%
R27 = RESISTOR
U35 = 74ALS573: Part Number: 20-00091
C24-C28 C30 C31 = CAP_NP: PSpice: C; Part Number: PCC220CNTR-ND; Voltage: 50V
E1 = B2S: Part Number: 70-00022
E2-E6 JP1 JP3 JP4 = B2S: Part Number: 70-00029
JP2 = HEADER_5X2: Part Number: 60-00047
P3 = IBMPC: Part Number: 70-00048
Q1 Q3-Q6 = NPN: PSpice: Q2N3904; Part Number: 85-00062
R29-R34 R39 R40 R43 R49-R53 R56 R60 = R: Part Number: ERJ-8GEYJ103V; Power: 1/8W; Tolerance: 5%
R35-R37 = R: Part Number: ERJ-6GEYJ220V; Power: 1/10W; Tolerance: 5%
R38 = R: Part Number: ERJ-8GEYJ105V; Power: 1/8W; Tolerance: 5%
U39 = 74HC244: PSpice: 74HCT244; Part Number: 20-000244
U40 U48-U50 U59 U65 = 22V10A: Part Number: TMP-1
U41 U42 U46 U47 U51 U52 = 6208S: Part Number: 20-00141
U43 = 74S133: Part Number: 20-00133
U44 = MC56001: Part Number: 20-003101
U45 U54 = 16L8: Part Number: 21-87201
U53 U56 = 74LS245: Part Number: 20-003296
U55 = 16C450FN: Part Number: 20-01287
Y2 = OSC8: Part Number: 20-00443
Y3 = CRYSTAL: Part Number: 20-00444
C29 C41 C51 C53 C57 C63 C64 C78 C102 C105 C117 = CAP: PSpice: C; Part Number: ECE-A1HKK0R1; Voltage: 50V
D3 = DIODE: PSpice: D; Part Number: 40-00018
JP5 P6 = HEADER_25X2: Part Number: 60-00042
P4 = CONNECTOR_DB25: Part Number: 70-00049
Q2 = PNP: PSpice: Q2N3906; Part Number: 85-00063
R41 R42 R54 = R: Part Number: ERJ-6GEYJ223V; Power: 1/10W; Tolerance: 5%
R44 R47 R48 = R: Part Number: ERJ-8GEYJ102V; Power: 1/8W; Tolerance: 5%
R45 = R: Part Number: ERJ-6GEYJ100V; Power: 1/10W; Tolerance: 5%
R46 = R: Part Number: ERJ-8GEYJ203V; Power: 1/8W; Tolerance: 5%
R55 = R: Part Number: ERJ-6GEYJ103V; Power: 1/10W; Tolerance: 5%
U57 U64 = 7201: Part Number: 20-00042
U58 = 74HC595: Part Number: 20-00595
U60 U67 U68 = 74HC163: Part Number: 20-00163
U61 = 27010A: Part Number: 20-01337
U62 = 74HC165: Part Number: 20-00165
U63 U72 = MC34051: Part Number: 20-003102
U66 U70 = 75176: Part Number: 20-00176
U69 = 74HC374: Part Number: 20-00374
U71 = 53C94: Part Number: 20-00094
C32 C36 C120 C121 = CAP_POL: PSpice: C; Part Number: ECE-A2AGE100; Voltage: 100V
C33 = CAP_POL: PSpice: C; Part Number: ECE-V1EA100SR; Voltage: 25V
C34 = SMALL_CAP: PSpice: C; Part Number: A104Z15Z5UFVVWN; Voltage: 50V
C35 C118 C119 C122 C124 C127 C135 = CAP_POL: PSpice: C; Part Number: ECE-V1HV100SP; Voltage: 50V
P5 = DIN96: Part Number: 70-00052
P7 = HEADER_8X2: Part Number: 60-00044
P8 = PC_AT_BUS: Part Number: 60-00043
P9 = HEADER_10: Part Number: 60-00041
U73 = 68HC11: Part Number: 20-00437
U75 = 74LS138: Part Number: TMP-3
U76 = 43256: Part Number: 20-00333
U77 = MC1413: Part Number: 20-003125
U78 = MC145407P: Part Number: 20-003122
U79 = MC34064: Part Number: 20-003119
Y4 = CRYSTAL: Part Number: 20-00445
C37 C40 C50 C74 C79 C81 C83 C89 C97 C103 C104 C129 = CAP: PSpice: C; Part Number: ECE-A1HKS0R1; Voltage: 50V
C38 C42 C45 C48 C49 C55 C68 C69 C71 C77 C85 C95 C106 C114 C133 C134 = CAP: PSpice: C; Part Number: ECE-A1HKA0R1; Voltage: 50V
C47 C59 C60 C66 C70 C84 C91 C93 C100 C111 = CAP: PSpice: C; Part Number: ECE-V1HA0R1SR; Voltage: 50V
C52 C72 C86 = CAP: PSpice: C; Part Number: ECE-A1HGE0R1; Voltage: 50V
C54 C61 C65 C73 C75 C76 C80 C87 C96 C99 C109 = CAP: PSpice: C; Part Number: ECE-V1HA0R1R; Voltage: 50V
C56 C58 C88 C94 C101 C108 C110 C112 C113 C115 C116 = CAP: PSpice: C; Part Number: ECE-V1HS0R1SR; Voltage: 50V
C123 C126 C128 C131 C132 = CAP_POL: PSpice: C; Part Number: ECG-C0JB100R; Voltage: 6.3V
C125 C136 = CAP_POL: PSpice: C; Part Number: ECE-V1HA100SP; Voltage: 50V

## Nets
+12V: P5.63(B31) P5.95(C31) P6.6 P7.12 P8.18(B09_+12V) U13.18(+VS) U14.4(V+) U15.18(+VS) U16.18(+VS)
-12V: U13.12(-VS) U14.11(V-) U15.12(-VS) U16.12(-VS)
-12V (page PAGE6): P5.62(B30) P5.94(C30) P6.8 P8.14(B07_-12V)
GND: C1.2 C2.2 C3.1 C4.1 C6.2 C7.2 C8.2 C9.2 C11.2 C12.2 C13.2 C14.2 C16.2 C17.2 C18.2 C19.2 C20.2 C21.2 C22.2 C23.2 C24.2 C25.2 C26.2 C27.2 C28.2 C29.2 C30.1 C31.1 C34.2 C35.1 C37.2 C38.2 C39.2 C40.2 C41.2 C42.2 C43.2 C44.2 C45.2 C46.2 C47.2 C48.2 C49.2 C50.2 C51.2 C52.2 C53.2 C54.2 C55.2 C56.2 C57.2 C58.2 C59.2 C60.2 C61.2 C62.2 C63.2 C64.2 C65.2 C66.2 C67.2 C68.2 C69.2 C70.2 C71.2 C72.2 C73.2 C74.2 C75.2 C76.2 C77.2 C78.2 C79.2 C80.2 C81.2 C82.2 C83.2 C84.2 C85.2 C86.2 C87.2 C88.2 C89.2 C90.2 C91.2 C92.2 C93.2 C94.2 C95.2 C96.2 C97.2 C98.2 C99.2 C100.2 C101.2 C102.2 C103.2 C104.2 C105.2 C106.2 C107.2 C108.2 C109.2 C110.2 C111.2 C112.2 C113.2 C114.2 C115.2 C116.2 C117.2 C118.2 C119.2 C120.2 C121.2 C122.2 C123.2 C124.2 C125.2 C126.2 C127.2 C128.2 C129.2 C130.2 C131.1 C132.1 C133.2 C134.2 C135.2 C136.2 E2.1 E3.1 E4.1 E5.1 E6.1 JP1.2 JP2.1 JP3.2 JP4.1 JP5.1 JP5.3 JP5.5 JP5.7 JP5.9 JP5.11 JP5.13 JP5.15 JP5.17 JP5.19 JP5.20 JP5.21 JP5.22 JP5.23 JP5.24 JP5.25 JP5.26 JP5.27 JP5.28 JP5.29 JP5.30 JP5.31 JP5.32 JP5.33 JP5.34 JP5.35 JP5.36 JP5.37 JP5.38 JP5.39 JP5.40 JP5.41 JP5.42 JP5.43 JP5.44 JP5.45 JP5.46 JP5.47 JP5.48 JP5.49 JP5.50 P2.8 P3.2(GND) P3.10(-5V) P3.62(GND2) P4.1 P4.4 P4.7 P4.10 P4.13 P4.15 P4.18 P4.21 P4.24 P5.34(B2) P5.35(B3) P5.36(B4) P5.37(B5) P5.38(B6) P5.39(B7) P5.40(B8) P5.41(B9) P5.42(B10) P5.43(B11) P5.44(B12) P5.45(B13) P5.46(B14) P5.47(B15) P5.48(B16) P5.49(B17) P5.50(B18) P5.51(B19) P5.52(B20) P5.53(B21) P5.54(B22) P5.55(B23) P5.56(B24) P5.57(B25) P5.58(B26) P5.59(B27) P5.60(B28) P5.61(B29) P7.15 P8.2(B01_GND) P8.20(B10_GND) P8.62(B31_GND) P8.98(D18_GND) P9.5 Q1.1 Q3.1 Q4.1 Q5.1 Q6.1 R5.2 R6.2 R7.2 R8.2 R11.2 R12.2 R13.2 R14.2 R17.2 R18.2 R19.2 R20.2 R28.2 R45.2 R56.1 S1.2 S2.1 U1.14(GND) U2.14(GND) U3.7(~{XI}) U3.14(GND) U4.14(GND) U5.14(GND) U6.7(~{XI}) U6.14(GND) U7.14(GND) U8.10(GND) U9.8(GND) U10.10(GND) U11.14(GND) U12.2(GND1) U12.10(GND2) U12.29(GND3) U12.49(GND4) U13.1(GND) U13.2(GND) U13.4(GND) U13.6(GND) U13.7(GND) U13.9(GND) U13.11(GND) U13.16(GND) U13.17(GND) U15.1(GND) U15.2(GND) U15.4(GND) U15.6(GND) U15.7(GND) U15.9(GND) U15.11(GND) U15.16(GND) U15.17(GND) U16.1(GND) U16.2(GND) U16.4(GND) U16.6(GND) U16.7(GND) U16.9(GND) U16.11(GND) U16.16(GND) U16.17(GND) U17.10(GND) U18.10(GND) U19.10(GND) U20.10(GND) U21.7(~{XI}) U21.14(GND) U22.10(GND) U23.10(GND) U24.10(GND) U25.10(GND) U26.7(~{XI}) U26.14(GND) U27.10(GND) U27.19(G) U28.10(GND) U29.10(GND) U30.10(GND) U31.10(GND) U31.19(G) U32.10(GND) U33.7(~{XI}) U33.14(GND) U34.14(GND) U35.1(OC) U35.2(D1) U35.10(GND) U36.14(GND) U37.7(~{XI}) U37.14(GND) U38.14(GND) U39.1(1G) U39.10(GND) U40.11(I9) U40.12(I10) U40.13(I11) U40.14(GND) U40.16(I12) U41.12(VSS) U42.12(VSS) U43.8(GND) U44.23(GND) U44.24(GND) U44.33(GND) U44.34(GND) U44.55(GND) U44.56(GND) U44.73(GND) U44.74(GND) U44.90(GND) U44.91(GND) U44.111(GND) U44.112(GND) U44.130(GND) U44.131(GND) U45.10(GND) U46.12(VSS) U47.12(VSS) U48.14(GND) U48.20(O7) U49.14(GND) U50.14(GND) U51.12(VSS) U52.12(VSS) U53.10(GND) U54.10(GND) U55.21(DOSTR) U55.22(GND) U55.25(DISTR) U55.28(/ADS) U55.39(MR) U56.5(A4) U56.10(GND) U56.19(G) U57.7(XI) U57.14(GND) U58.8(GND) U59.5(I4) U59.6(I5) U59.7(I6) U59.9(I7) U59.10(I8) U59.11(I9) U59.12(I10) U59.13(I11) U59.14(GND) U59.16(I12) U60.8(GND) U61.16(GND) U61.22(~{CE}) U61.24(~{OE}) U62.8(GND) U62.10(SER) U62.15(INH) U63.8(GND) U64.7(XI) U64.14(GND) U65.7(I6) U65.9(I7) U65.10(I8) U65.14(GND) U66.5(GND) U67.8(GND) U68.8(GND) U69.10(GND) U69.14(D5) U69.17(D6) U69.18(D7) U70.5(GND) U71.2(VSS) U71.22(VSS) U71.27(VSS) U71.33(VSS) U71.34(SELO) U71.35(BSYO) U71.36(REQO) U71.37(ACKO) U71.38(VSS) U71.39(MSGIO) U71.40(C/DIO) U71.41(I/OIO) U71.42(ATNIO) U71.43(RSTO) U71.44(VSS) U71.45(SELI) U71.46(BSYI) U71.47(REQI) U71.48(ACKI) U71.49(RSTI) U71.53(RESET) U71.67(VSS) U71.75(VSS) U71.76(VSS) U72.8(GND) U73.1(VSS) U73.67(VRL) U74.14(GND) U75.4(G2A) U75.8(GND) U76.14(GND) U77.8(GND) U78.2(GND) U79.3(GND) U80.10(GND) Y2.4(GND)
GND2: J1.2(GND2) J2.2(GND2) J3.2(GND2)
GND3: J1.3(GND3) J2.3(GND3) J3.3(GND3)
GND4: J1.4(GND4) J2.4(GND4) J3.4(GND4)
GND5: J1.5(GND5) J2.5(GND5) J3.5(GND5)
+5: C36.2 C37.1 C38.1 C39.1 C40.1 C41.1 C42.1 C43.1 C44.1 C45.1 C46.1 C47.1 C48.1 C49.1 C50.1 C51.1 C52.1 C53.1 C54.1 C55.1 C56.1 C57.1 C58.1 C59.1 C60.1 C61.1 C62.1 C63.1 C64.1 C65.1 C66.1 C67.1 C68.1 C69.1 C70.1 C71.1 C72.1 C73.1 C74.1 C75.1 C76.1 C77.1 C78.1 C79.1 C80.1 C81.1 C82.1 C83.1 C84.1 C85.1 C86.1 C87.1 C88.1 C89.1 C90.1 C91.1 C92.1 C93.1 C94.1 C95.1 C96.1 C97.1 C98.1 C99.1 C100.1 C101.1 C102.1 C103.1 C104.1 C105.1 C106.1 C107.1 C108.1 C109.1 C110.1 C111.1 C112.1 C113.1 C114.1 C115.1 C116.1 C117.1 C118.1 C119.1 C120.1 C121.1 C122.1 C123.1 C124.1 C125.1 C126.1 C127.1 C128.1 D3.2 P2.1 P3.6(+5V) P3.58(+5V(2)) P5.1(A1) P5.32(A32) P5.33(B1) P5.64(B32) P5.65(C1) P5.96(C32) P6.2 P6.4 P7.16 P8.6(B03_+5V) P8.58(B29_+5V) P8.94(D16_+5V) R3.2 R22.2 R27.2 R29.2 R30.1 R31.1 R32.1 R33.1 R40.1 R43.1 R45.1 R48.1 R52.1 R53.1 R54.1 R57.1 R61.1 U1.28(VCC) U2.28(VCC) U3.23(~{FL}/~{RT}) U3.28(VCC) U4.28(VCC) U5.28(VCC) U6.23(~{FL}/~{RT}) U6.28(VCC) U7.28(VCC) U8.20(VCC) U9.16(VCC) U10.1(DIR) U10.20(VCC) U11.28(VCC) U12.16(VCC1) U12.26(VCC2) U12.57(VCC3) U13.15(EN) U15.15(EN) U16.15(EN) U17.1(DIR) U17.20(VCC) U18.20(VCC) U19.20(VCC) U20.20(VCC) U21.23(~{FL}/~{RT}) U21.28(VCC) U22.1(DIR) U22.20(VCC) U23.20(VCC) U24.1(DIR) U24.20(VCC) U25.20(VCC) U26.23(~{FL}/~{RT}) U26.28(VCC) U27.20(VCC) U28.20(VCC) U29.1(DIR) U29.20(VCC) U30.1(DIR) U30.20(VCC) U31.20(VCC) U32.1(DIR) U32.20(VCC) U33.23(~{FL}/~{RT}) U33.28(VCC) U34.28(VCC) U35.20(VCC) U36.28(VCC) U37.23(~{FL}/~{RT}) U37.28(VCC) U38.28(VCC) U39.12(1Y4) U39.16(1Y2) U39.20(VCC) U40.28(VCC) U41.24(VCC) U42.24(VCC) U43.1(I0) U43.2(I1) U43.16(VCC) U44.12(VCC) U44.13(VCC) U44.35(VCC) U44.36(VCC) U44.63(VCC) U44.64(VCC) U44.100(VCC) U44.101(VCC) U44.128(VCC) U44.129(VCC) U45.20(VCC) U46.24(VCC) U47.24(VCC) U48.28(VCC) U49.28(VCC) U50.28(VCC) U51.24(VCC) U52.24(VCC) U53.20(VCC) U54.20(VCC) U55.14(CS0) U55.15(CS1) U55.44(VCC) U56.1(DIR) U56.20(VCC) U57.2(D8) U57.23(FL/RT) U57.28(VCC) U58.10(SRCLR) U58.11(SRCLK) U58.16(VCC) U59.2(I1/CLK) U59.4(I3) U59.28(VCC) U60.1(CLR) U60.2(CLK) U60.3(A) U60.4(B) U60.5(C) U60.6(D) U60.7(ENP) U60.9(LOAD) U60.10(ENT) U60.15(RCO) U60.16(VCC) U61.1(VPP) U61.30(NC) U61.31(/PGM) U61.32(VCC) U62.2(CLK) U62.16(VCC) U63.9(T) U63.16(VCC) U64.2(D8) U64.23(FL/RT) U64.28(VCC) U65.2(I1/CLK) U65.28(VCC) U66.8(VCC) U67.1(CLR) U67.2(CLK) U67.3(A) U67.4(B) U67.5(C) U67.6(D) U67.7(ENP) U67.9(LOAD) U67.10(ENT) U67.15(RCO) U67.16(VCC) U68.1(CLR) U68.2(CLK) U68.3(A) U68.4(B) U68.5(C) U68.6(D) U68.7(ENP) U68.9(LOAD) U68.10(ENT) U68.16(VCC) U69.20(VCC) U70.8(VCC) U71.21(VDD) U71.50(MODE1) U71.51(MODE0) U71.62(VDD) U72.16(VCC) U73.34(VDD) U74.28(VCC) U75.6(G1) U75.16(VCC) U76.28(VCC) U78.19(VCC) U79.2(VCC) U80.20(VCC) Y2.8(+5)
/READ: U48.6(I5) U49.6(I5) U55.20(/DOSTR) U56.17(B2) U71.55(RD)
/WRITE: U44.9(HR/W) U48.7(I6) U49.7(I6) U55.24(/DISTR) U56.16(B3) U71.54(WR)
A0: U41.1(A0) U42.1(A0) U44.53(A0) U46.1(A0) U47.1(A0) U51.1(A0) U52.1(A0)
A1: U41.2(A1) U42.2(A1) U44.54(A1) U46.2(A1) U47.2(A1) U50.3(I2) U51.2(A1) U52.2(A1)
A2: U41.3(A2) U42.3(A2) U44.57(A2) U46.3(A2) U47.3(A2) U50.4(I3) U51.3(A2) U52.3(A2)
A3: U41.4(A3) U42.4(A3) U44.58(A3) U46.4(A3) U47.4(A3) U50.5(I4) U51.4(A3) U52.4(A3)
A4: U41.5(A4) U42.5(A4) U44.60(A4) U46.5(A4) U47.5(A4) U50.6(I5) U51.5(A4) U52.5(A4)
A5: U41.6(A5) U42.6(A5) U43.3(I2) U44.61(A5) U46.6(A5) U47.6(A5) U51.6(A5) U52.6(A5)
A6: U41.7(A6) U42.7(A6) U43.4(I3) U44.65(A6) U46.7(A6) U47.7(A6) U51.7(A6) U52.7(A6)
A7: U41.8(A7) U42.8(A7) U43.5(I4) U44.67(A7) U46.8(A7) U47.8(A7) U51.8(A7) U52.8(A7)
A8: U41.9(A8) U42.9(A8) U43.6(I5) U44.68(A8) U46.9(A8) U47.9(A8) U51.9(A8) U52.9(A8)
A9: U41.10(A9) U42.10(A9) U43.7(I6) U44.70(A9) U46.10(A9) U47.10(A9) U51.10(A9) U52.10(A9)
A10: U41.18(A10) U42.18(A10) U43.10(I7) U44.71(A10) U46.18(A10) U47.18(A10) U51.18(A10) U52.18(A10)
A11: U43.11(I8) U44.75(A11) U45.6(I6)
A12: U43.12(I9) U44.76(A12) U45.5(I5)
A13: U43.13(I10) U44.77(A13) U45.4(I4)
A14: U43.14(I11) U44.79(A14) U45.3(I3)
A15: U43.15(I12) U44.80(A15) U45.2(I2)
AA0: P3.61(SA0) U56.6(A5)
AA1: P3.59(SA1) U56.7(A6)
AA2: P3.57(SA2) U56.8(A7)
AA3: P3.55(SA3) U56.9(A8)
ADC-: P6.30 U9.12(Y3)
AEN: P5.11(A11) P8.21(AEN_A11) U34.11(I9) U36.2(I1/CLK) U38.16(I12)
BALE: P5.87(C23) P8.56(B28_BALE) U35.11(C)
BG-: U11.9(I7) U12.40(~{BG}) U17.19(G) U22.19(G) U34.10(I8) U38.10(I8)
BK0: U41.19(A11) U42.19(A11) U45.15(O5) U46.19(A11) U47.19(A11) U51.19(A11) U52.19(A11)
BK1: U41.20(A12) U42.20(A12) U45.16(O4) U46.20(A12) U47.20(A12) U51.20(A12) U52.20(A12)
BK2: U41.21(A13) U42.21(A13) U45.17(O3) U46.21(A13) U47.21(A13) U51.21(A13) U52.21(A13)
BK3: U41.22(A14) U42.22(A14) U45.18(O2) U46.22(A14) U47.22(A14) U51.22(A14) U52.22(A14)
BK4: U41.23(A15) U42.23(A15) U45.19(O1) U46.23(A15) U47.23(A15) U51.23(A15) U52.23(A15)
BMS-: U11.5(I4) U11.24(O4) U12.39(~{BMS})
BOARD_RD-: U27.1(DIR) U31.1(DIR) U38.25(O3)
BR-: U12.18(~{BR}) U20.6(Q3)
C0: U60.11(QD) U61.12(A0) U69.3(D0)
C1: U61.11(A1) U67.14(QA) U69.4(D1)
C2: U61.10(A2) U67.13(QB) U69.7(D2)
C3: U61.9(A3) U67.12(QC) U69.8(D3)
C4: U61.8(A4) U67.11(QD) U69.13(D4)
C5: U61.7(A5) U68.14(QA)
C6: U61.6(A6) U68.13(QB)
C7: U61.5(A7) U68.12(QC)
C8: U61.27(A8) U68.11(QD)
C9: U59.27(O1) U61.26(A9)
C10: U59.19(O8) U61.23(A10)
C11: U59.26(O2) U61.25(A11)
C12: U59.20(O7) U61.4(A12)
C13: U59.25(O3) U61.28(A13)
C14: U59.21(O6) U61.29(A14)
C15: U59.24(O4) U61.3(A15)
C16: U59.23(O5) U61.2(A16)
CLKOUT: TP2.1 U11.2(I1/CLK) U12.43(CLKOUT)
D0: U13.14(A0) U41.17(D0) U44.81(D0) U50.26(O2) U55.2(D0) U64.9(Q0) U71.77(DB0)
D1: U13.13(A1) U41.16(D1) U44.82(D1) U55.3(D1) U64.10(Q1) U71.78(DB1)
D2: U15.14(A0) U41.15(D2) U44.85(D2) U55.4(D2) U64.11(Q2) U71.79(DB2)
D3: U15.13(A1) U41.14(D3) U44.86(D3) U55.5(D3) U64.12(Q3) U71.80(DB3)
D4: U16.14(A0) U44.87(D4) U46.17(D0) U55.6(D4) U64.16(Q4) U71.81(DB4)
D5: U16.13(A1) U44.88(D5) U46.16(D1) U55.7(D5) U64.17(Q5) U71.82(DB5)
D6: U44.92(D6) U46.15(D2) U55.8(D6) U64.18(Q6) U71.83(DB6)
D7: U44.93(D7) U46.14(D3) U55.9(D7) U64.19(Q7) U71.84(DB7)
D8: U44.94(D8) U51.17(D0) U71.3(DB8)
D9: U44.96(D9) U51.16(D1) U71.4(DB9)
D10: U44.97(D10) U51.15(D2) U71.5(DB10)
D11: U44.99(D11) U51.14(D3) U71.6(DB11)
D12: U42.17(D0) U44.102(D12) U71.7(DB12)
D13: U42.16(D1) U44.104(D13) U71.8(DB13)
D14: U42.15(D2) U44.105(D14) U71.9(DB14)
D15: U42.14(D3) U44.106(D15) U71.10(DB15)
D16: U44.108(D16) U47.17(D0)
D17: U44.109(D17) U47.16(D1)
D18: U44.113(D18) U47.15(D2)
D19: U44.114(D19) U47.14(D3)
D20: U44.115(D20) U52.17(D0)
D21: U44.118(D21) U52.16(D1)
D22: U44.119(D22) U52.15(D2)
D23: R28.1 U44.120(D23) U52.14(D3)
DACK7-: P5.92(C28) P8.90(D14_~{DACK}7) U34.12(I10)
DATA_OUT: P6.24 U73.33(PD5/~{SS})
DMS-: U2.20(~{CS1}) U5.20(~{CS1}) U11.4(I3) U11.26(O2) U12.38(~{DMS})
DRQ7: P5.93(C29) P8.92(D15_DRQ7) U34.19(O8)
DSP_A0: U1.10(A0) U2.10(A0) U4.10(A0) U5.10(A0) U7.10(A0) U9.1(A) U12.21(A0) U17.18(B1)
DSP_A1: U1.9(A1) U2.9(A1) U4.9(A1) U5.9(A1) U7.9(A1) U9.2(B) U12.22(A1) U17.17(B2)
DSP_A2: U1.8(A2) U2.8(A2) U4.8(A2) U5.8(A2) U7.8(A2) U9.3(C) U12.23(A2) U17.16(B3)
DSP_A3: P6.34 U1.7(A3) U2.7(A3) U4.7(A3) U5.7(A3) U7.7(A3) U12.24(A3) U17.15(B4)
DSP_A4: U1.6(A4) U2.6(A4) U4.6(A4) U5.6(A4) U7.6(A4) U12.25(A4) U17.14(B5)
DSP_A5: U1.5(A5) U2.5(A5) U4.5(A5) U5.5(A5) U7.5(A5) U12.27(A5) U17.13(B6)
DSP_A6: U1.4(A6) U2.4(A6) U4.4(A6) U5.4(A6) U7.4(A6) U12.28(A6) U17.12(B7)
DSP_A7: U1.3(A7) U2.3(A7) U4.3(A7) U5.3(A7) U7.3(A7) U12.30(A7) U17.11(B8)
DSP_A8: U1.25(A8) U2.25(A8) U4.25(A8) U5.25(A8) U7.25(A8) U12.31(A8) U22.18(B1)
DSP_A9: U1.24(A9) U2.24(A9) U4.24(A9) U5.24(A9) U7.24(A9) U12.32(A9) U22.17(B2)
DSP_A10: U1.21(A10) U2.21(A10) U4.21(A10) U5.21(A10) U7.21(A10) U12.33(A10) U22.16(B3)
DSP_A11: U1.23(A11) U2.23(A11) U4.23(A11) U5.23(A11) U7.23(A11) U9.4(G2A) U11.16(I12) U12.34(A11) U22.15(B4)
DSP_A12: U1.2(A12) U2.2(A12) U4.2(A12) U5.2(A12) U7.2(A12) U9.5(G2B) U11.21(O6) U12.35(A12) U22.14(B5)
DSP_A13: U11.10(I8) U12.36(A13) U22.13(B6) U38.11(I9)
DSP_A13-: U2.26(CS2) U5.26(CS2) U11.18(O9)
DSP_A14: U11.11(I9) U22.12(B7) U38.12(I10)
DSP_A15: U11.12(I10) U22.11(B8) U38.13(I11)
DSP_BUFFER-: U9.9(Y6) U10.19(G)
DSP_D0: U1.11(D0) U12.58(D0) U13.3(IN1) U18.18(B1)
DSP_D1: U1.12(D1) U12.59(D1) U13.5(IN2) U18.17(B2)
DSP_D2: U1.13(D2) U12.60(D2) U13.8(IN3) U18.16(B3)
DSP_D3: U1.15(D3) U12.61(D3) U15.3(IN1) U18.15(B4)
DSP_D4: U1.16(D4) U12.62(D4) U15.5(IN2) U18.14(B5)
DSP_D5: U1.17(D5) U12.63(D5) U15.8(IN3) U18.13(B6)
DSP_D6: U1.18(D6) U12.64(D6) U16.3(IN1) U18.12(B7)
DSP_D7: U1.19(D7) U12.65(D7) U16.5(IN2) U18.11(B8)
DSP_D8: P6.1 U2.11(D0) U4.11(D0) U8.3(D1) U10.18(B1) U12.66(D8) U16.8(IN3) U21.6(D0) U23.18(B1) U33.9(Q0)
DSP_D9: P6.3 U2.12(D1) U4.12(D1) U8.4(D2) U10.17(B2) U12.67(D9) U21.5(D1) U23.17(B2) U33.10(Q1)
DSP_D10: P6.5 U2.13(D2) U4.13(D2) U8.7(D3) U10.16(B3) U12.68(D10) U21.4(D2) U23.16(B3) U33.11(Q2)
DSP_D11: P6.7 U2.15(D3) U4.15(D3) U8.8(D4) U10.15(B4) U12.1(D11) U21.3(D3) U23.15(B4) U33.12(Q3)
DSP_D12: P6.9 U2.16(D4) U4.16(D4) U8.13(D5) U10.14(B5) U12.3(D12) U21.27(D4) U23.14(B5) U33.16(Q4)
DSP_D13: P6.11 U2.17(D5) U4.17(D5) U8.14(D6) U10.13(B6) U12.4(D13) U21.26(D5) U23.13(B6) U33.17(Q5)
DSP_D14: P6.13 U2.18(D6) U4.18(D6) U8.17(D7) U10.12(B7) U12.5(D14) U21.25(D6) U23.12(B7) U33.18(Q6)
DSP_D15: P6.15 U2.19(D7) U4.19(D7) U8.18(D8) U10.11(B8) U12.6(D15) U21.24(D7) U23.11(B8) U33.19(Q7)
DSP_D16: P6.17 U5.11(D0) U7.11(D0) U12.7(D16) U26.6(D0) U28.18(B1) U37.9(Q0)
DSP_D17: P6.19 U5.12(D1) U7.12(D1) U12.8(D17) U26.5(D1) U28.17(B2) U37.10(Q1)
DSP_D18: P6.21 U5.13(D2) U7.13(D2) U12.9(D18) U26.4(D2) U28.16(B3) U37.11(Q2)
DSP_D19: P6.23 U5.15(D3) U7.15(D3) U12.11(D19) U26.3(D3) U28.15(B4) U37.12(Q3)
DSP_D20: P6.25 U5.16(D4) U7.16(D4) U12.12(D20) U26.27(D4) U28.14(B5) U37.16(Q4)
DSP_D21: P6.27 U5.17(D5) U7.17(D5) U12.13(D21) U26.26(D5) U28.13(B6) U37.17(Q5)
DSP_D22: P6.29 U5.18(D6) U7.18(D6) U12.14(D22) U26.25(D6) U28.12(B7) U37.18(Q6)
DSP_D23: P6.31 U5.19(D7) U7.19(D7) U12.15(D23) U26.24(D7) U28.11(B8) U37.19(Q7)
DSP_F1_EM-: P1.2 U10.6(A5) U21.21(~{EF}) U30.2(A1) U34.16(I12)
DSP_F1_FL-: U10.8(A7) U21.8(~{FF}) U30.6(A5)
DSP_F1_RD-: C20.1 R23.2 U21.15(~{R}) U26.15(~{R})
DSP_F1_RS-: U20.9(Q4) U21.22(~{RS}) U26.22(~{RS})
DSP_F1_WR-: C1.1 R1.2 U21.1(~{W}) U26.1(~{W})
DSP_F2_EM-: P1.6 U10.7(A6) U30.3(A2) U33.21(~{EF})
DSP_F2_FL-: U10.9(A8) U30.7(A6) U33.8(~{FF})
DSP_F2_RD-: C2.1 R2.2 U33.15(~{R}) U37.15(~{R})
DSP_F2_RS-: U9.13(Y2) U33.22(~{RS}) U37.22(~{RS})
DSP_F2_WR-: C21.1 R24.2 U33.1(~{W}) U37.1(~{W})
DSP_IO: U9.6(G1) U11.23(O5)
DSP_LATCH-: U8.11(CLK) U9.10(Y5)
DSP_RD-: U1.22(~{OE}) U2.22(~{OE}) U4.22(~{OE}) U5.22(~{OE}) U7.22(~{OE}) U11.6(I5) U12.45(~{RD}) U18.1(DIR) U23.1(DIR) U28.1(DIR) U38.24(O4)
DSP_SPI_CLK: U12.56(SCLK1) U74.27(O1)
DSP_SPI_IN: U12.55(DR1) U74.10(I8)
DSP_WR-: U1.27(~{WE}) U2.27(~{WE}) U4.27(~{WE}) U5.27(~{WE}) U7.27(~{WE}) U11.7(I6) U12.44(~{WR}) U38.23(O5)
DSPHC111: U8.6(Q3) U73.23(PG4/CSIO2)
DSPHC112: U8.9(Q4) U73.22(PG5/CSIO1)
DSPPC1: U8.2(Q1) U32.2(A1)
DSPPC2: U8.5(Q2) U32.3(A2)
E: U41.11(E) U42.11(E) U45.14(O6) U46.11(E) U47.11(E) U51.11(E) U52.11(E)
FLASH_WE-: R27.1 U34.17(O10)
FREQ_MOD: P6.22 U73.40(PA2/IC1)
H0: U39.3(2Y4) U44.25(H0) U53.18(B1) U57.9(Q0) U71.63(PAD0)
H1: U39.5(2Y3) U44.22(H1) U53.17(B2) U57.10(Q1) U71.64(PAD1)
H2: U39.7(2Y2) U44.20(H2) U53.16(B3) U57.11(Q2) U71.65(PAD2)
H3: U39.9(2Y1) U44.19(H3) U53.15(B4) U57.12(Q3) U71.66(PAD3)
H4: U40.27(O1) U44.16(H4) U53.14(B5) U57.16(Q4) U71.68(PAD4)
H5: U44.15(H5) U53.13(B6) U57.17(Q5) U71.69(PAD5)
H6: U44.14(H6) U53.12(B7) U57.18(Q6) U71.70(PAD6)
H7: U44.11(H7) U53.11(B8) U57.19(Q7) U71.71(PAD7)
HA0: U44.5(HA0) U55.31(A0) U56.14(B5) U71.57(A0)
HA1: U44.2(HA1) U55.30(A1) U56.13(B6) U71.58(A1)
HA2: U44.1(HA2) U55.29(A2) U56.12(B7) U71.59(A2)
HA3: U48.13(I11) U49.11(I9) U54.13(O7) U56.11(B8) U71.60(A3)
HC11_A0: U24.18(B1) U73.58(A0/PF0) U75.1(A) U76.10(A0)
HC11_A1: U24.17(B2) U73.57(A1/PF1) U75.2(B) U76.9(A1)
HC11_A2: U24.16(B3) U73.56(A2/PF2) U74.5(I4) U75.3(C) U76.8(A2)
HC11_A3: U24.15(B4) U73.55(A3/PF3) U76.7(A3)
HC11_A4: U24.14(B5) U73.54(A4/PF4) U76.6(A4)
HC11_A5: U24.13(B6) U73.53(A5/PF5) U76.5(A5)
HC11_A6: U24.12(B7) U73.52(A6/PF6) U76.4(A6)
HC11_A7: U24.11(B8) U73.51(A7/PF7) U76.3(A7)
HC11_A8: U29.18(B1) U73.50(A8/PB0) U76.25(A8)
HC11_A9: U29.17(B2) U73.49(A9/PB1) U76.24(A9)
HC11_A10: U29.16(B3) U73.48(A10/PB2) U76.21(A10)
HC11_A11: U29.15(B4) U73.47(A11/PB3) U76.23(A11)
HC11_A12: U29.14(B5) U73.46(A12/PB4) U76.2(A12)
HC11_A13: U29.13(B6) U73.45(A13/PB5) U76.26(A13)
HC11_A14: U29.12(B7) U73.44(A14/PB6) U76.1(A14)
HC11_A15: U29.11(B8) U73.43(A15/PB7)
HC11_D0: P6.33 U3.6(D0) U6.9(Q0) U19.18(B1) U73.9(D0/PC0) U76.11(O0) U80.2(A1)
HC11_D1: P6.35 U3.5(D1) U6.10(Q1) U19.17(B2) U73.10(D1/PC1) U76.12(O1) U80.3(A2)
HC11_D2: P6.37 U3.4(D2) U6.11(Q2) U19.16(B3) U73.11(D2/PC2) U76.13(O2) U80.4(A3)
HC11_D3: P6.39 U3.3(D3) U6.12(Q3) U19.15(B4) U73.12(D3/PC3) U76.15(O3) U80.5(A4)
HC11_D4: P6.41 U3.27(D4) U6.16(Q4) U19.14(B5) U73.13(D4/PC4) U76.16(O4) U80.6(A5)
HC11_D5: P6.43 U3.26(D5) U6.17(Q5) U19.13(B6) U73.14(D5/PC5) U76.17(O5)
HC11_D6: P6.45 U3.25(D6) U6.18(Q6) U19.12(B7) U73.15(D6/PC6) U76.18(O6)
HC11_D7: P6.47 U3.24(D7) U6.19(Q7) U19.11(B8) U73.16(D7/PC7) U76.19(O7)
HC11_F1_EM-: P1.4 U3.21(~{EF}) U30.4(A3) U73.63(PE2/AN2)
HC11_F1_FL-: U3.8(~{FF}) U30.8(A7) U73.60(PE4/AN4)
HC11_F1_RD-: C22.1 R25.2 U3.15(~{R})
HC11_F1_RS-: U3.22(~{RS}) U25.5(Q2)
HC11_F1_WR-: U3.1(~{W}) U75.10(Y5)
HC11_F2_EM-: P1.8 U6.21(~{EF}) U30.5(A4) U73.65(PE3/AN3)
HC11_F2_FL-: U6.8(~{FF}) U30.9(A8) U73.62(PE5/AN5)
HC11_F2_RD-: U6.15(~{R}) U75.11(Y4)
HC11_F2_RS-: U6.22(~{RS}) U75.9(Y6)
HC11_F2_WR-: C23.1 R26.2 U6.1(~{W})
HC11_MEM_RD-: U19.1(DIR) U38.19(O8)
HC11_MODE: R58.1 R59.1 U38.2(I1/CLK) U78.16(DO1)
HC11_RAM_CS-: U74.23(O5) U76.20(~{CE})
HC11_RAM_OE-: U74.20(O7) U76.22(~{OE})
HC11_RAM_WE-: U74.21(O6) U76.27(~{WE})
HC11_RXD: U73.28(PD0/RXD) U78.12(DO3)
HC11_TXD: U73.29(PD1/TXD) U78.11(DI3)
HC11DSP1: U10.4(A3) U73.25(PG2)
HC11DSP2: U10.5(A4) U73.24(PG3)
HC11PC1: U32.4(A3) U73.27(PG0)
HC11PC2: U32.5(A4) U73.26(PG1)
IO-: U34.7(I6) U36.27(O1) U38.7(I6)
IOCHRDY: P5.10(A10) P8.19(IOCHRDY_A10) U34.26(O2)
IOCS16-: P5.84(C20) P8.66(D02_~{IOCS16}) U34.27(O1)
IOR-: P5.89(C25) P8.28(B14_~{IOR}) U34.5(I4) U38.5(I4)
IOW-: P5.88(C24) P8.26(B13_~{IOW}) U34.6(I5) U38.6(I5)
IRQ_DSP-: P1.1 P1.5 TP3.1 U12.19(~{IRQ2}) U20.15(Q6)
IRQ_HC11-: P1.7 U20.16(Q7) U73.19(~{IRQ})
L/R-: U73.41(PA1/IC2) U74.4(I3)
L_IR_SEEN: P6.28 U73.61(PE1/AN1)
L_RX_LATCH-: P6.14 U75.13(Y2)
L_SPI_CLK: P6.20 U74.25(O3)
L_TX_LATCH-: P6.16 U75.12(Y3)
LA17: P5.72(C8) P8.77(LA17_C08) U35.3(D2)
LA18: P5.71(C7) P8.75(LA18_C07) U35.4(D3)
LA19: P5.70(C6) P8.73(LA19_C06) U35.5(D4)
LA20: P5.69(C5) P8.71(LA20_C05) U35.6(D5)
LA21: P5.68(C4) P8.69(LA21_C04) U35.7(D6)
LA22: P5.67(C3) P8.67(LA22_C03) U35.8(D7)
LA23: P5.66(C2) P8.65(LA23_C02) U35.9(D8)
LAMP1: U73.39(PA3/OC5/IC4/OC1) U77.1(IN1)
LAMP1-: P7.2 U77.16(OUT1)
LAMP2: U73.38(PA4/OC4/OC1) U77.2(IN2)
LAMP2-: P7.4 U77.15(OUT2)
LAMP3: U73.37(PA5/OC3/OC1) U77.3(IN3)
LAMP3-: P7.6 U77.14(OUT3)
LAMP4: U73.36(PA6/OC2/OC1) U77.4(IN4)
LAMP4-: P7.8 U77.13(OUT4)
LAMP5: U73.35(PA7/PAI/OC1) U77.5(IN5)
LAMP5-: P7.10 U77.12(OUT5)
MEM-: U34.9(I7) U36.26(O2) U38.9(I7) U74.9(I7)
MEMCS16-: P5.83(C19) P8.64(D01_~{MEMCS16}) U36.17(O10)
MEMR-: P5.73(C9) P8.79(~{MEMR}_C09) U34.3(I2) U38.3(I2) U74.6(I5)
MEMW-: P5.74(C10) P8.81(~{MEMW}_C10) U34.4(I3) U38.4(I3) U74.7(I6)
MISO: U12.52(DT1) U73.30(PD2/MISO) U74.24(O4)
MMAP: U12.17(MMAP) U20.5(Q2)
N0: U57.6(D0) U58.1(QB) U64.6(D0) U69.2(Q0)
N1: U57.5(D1) U58.2(QC) U64.5(D1) U69.5(Q1)
N2: U57.4(D2) U58.3(QD) U64.4(D2) U69.6(Q2)
N3: U57.3(D3) U58.4(QE) U64.3(D3) U65.11(I9) U69.9(Q3)
N4: U57.27(D4) U58.5(QF) U64.27(D4) U65.12(I10) U69.12(Q4)
N5: U57.26(D5) U58.6(QG) U64.26(D5) U65.13(I11) U69.15(Q5)
N6: U57.25(D6) U58.7(QH) U64.25(D6) U65.16(I12) U69.16(Q6)
PC_A0: P5.31(A31) P8.61(SA0_A31)
PC_A1: P5.30(A30) P8.59(SA1_A30) U17.2(A1) U24.2(A1) U34.2(I1/CLK) U36.11(I9)
PC_A2: P5.29(A29) P8.57(SA2_A29) U17.3(A2) U24.3(A2) U34.13(I11) U36.12(I10)
PC_A3: P5.28(A28) P8.55(SA3_A28) U17.4(A3) U24.4(A3) U36.13(I11)
PC_A4: P5.27(A27) P8.53(SA4_A27) U17.5(A4) U24.5(A4) U36.16(I12) U36.25(O3)
PC_A5: P5.26(A26) P8.51(SA5_A26) U17.6(A5) U24.6(A5) U36.24(O4)
PC_A6: P5.25(A25) P8.49(SA6_A25) U17.7(A6) U24.7(A6) U36.23(O5)
PC_A7: P5.24(A24) P8.47(SA7_A24) U17.8(A7) U24.8(A7) U36.21(O6)
PC_A8: P5.23(A23) P8.45(SA8_A23) U17.9(A8) U24.9(A8) U36.20(O7)
PC_A9: P5.22(A22) P8.43(SA9_A22) U22.2(A1) U29.2(A1) U36.19(O8)
PC_A10: P5.21(A21) P8.41(SA10_A21) U22.3(A2) U29.3(A2)
PC_A11: P5.20(A20) P8.39(SA11_A20) U22.4(A3) U29.4(A3)
PC_A12: P5.19(A19) P8.37(SA12_A19) U22.5(A4) U29.5(A4)
PC_A13: P5.18(A18) P8.35(SA13_A18) U22.6(A5) U29.6(A5)
PC_A14: P5.17(A17) P8.33(SA14_A17) U22.7(A6) U29.7(A6)
PC_A15: P5.16(A16) P8.31(SA15_A16) U22.8(A7) U29.8(A7)
PC_A16: P5.15(A15) P8.29(SA16_A15) U22.9(A8) U29.9(A8) U36.18(O9)
PC_A17: P5.14(A14) P8.27(SA17_A14)
PC_A18: P5.13(A13) P8.25(SA18_A13)
PC_A19: P5.12(A12) P8.23(SA19_A12)
PC_D0: P5.9(A9) P8.17(SD0_A09) U27.2(A1)
PC_D1: P5.8(A8) P8.15(SD1_A08) U27.3(A2)
PC_D2: P5.7(A7) P8.13(SD2_A07) U27.4(A3)
PC_D3: P5.6(A6) P8.11(SD3_A06) U27.5(A4)
PC_D4: P5.5(A5) P8.9(SD4_A05) U27.6(A5)
PC_D5: P5.4(A4) P8.7(SD5_A04) U27.7(A6)
PC_D6: P5.3(A3) P8.5(SD6_A03) U27.8(A7)
PC_D7: P5.2(A2) P8.3(SD7_A02) U27.9(A8)
PC_D8: P5.75(C11) P8.83(SD8_C11) U31.2(A1)
PC_D9: P5.76(C12) P8.85(SD9_C12) U31.3(A2)
PC_D10: P5.77(C13) P8.87(SD10_C13) U31.4(A3)
PC_D11: P5.78(C14) P8.89(SD11_C14) U31.5(A4)
PC_D12: P5.79(C15) P8.91(SD12_C15) U31.6(A5)
PC_D13: P5.80(C16) P8.93(SD13_C16) U31.7(A6)
PC_D14: P5.81(C17) P8.95(SD14_C17) U31.8(A7)
PC_D15: P5.82(C18) P8.97(SD15_C18) U31.9(A8)
PC_IRQ9: P1.9 P5.91(C27) P8.8(B04_IRQ9)
PC_IRQ10: P1.11 P5.85(C21) P8.68(D03_IRQ10)
PC_REG-: U20.11(CLK) U25.11(CLK) U34.25(O3)
PC_RESET: P5.90(C26) P8.4(B02_RESET) U11.13(I11)
PC_RESET-: U8.1(CLR) U11.19(O8) U20.1(CLR) U25.1(CLR)
PC_STATUS-: U30.19(G) U32.19(G) U34.18(O9)
PCD1: U39.17(2A4) U40.3(I2) U57.21(EF)
PCD2: U48.25(O3) U57.15(R)
PCD3: U48.24(O4) U57.22(RESET) U64.22(RESET)
PCD6: R46.2 U49.25(O3)
PCD7: R50.1 U44.124(RESET) U49.24(O4)
PCD8: R51.1 U39.6(1A3) U39.8(1A4) U44.40(SC1) U70.1(R) U70.4(D)
PCD9: U39.2(1A1) U39.4(1A2) U44.31(SC0) U44.32(SCK) U66.1(R) U66.4(D)
PCD10: Q4.3 R47.1 U44.121(MODB/IRQB/NMI)
PCD11: Q6.3 R54.2 U44.123(MODA/IRQA)
PCD12: U44.27(RXD) U63.5(R)
PCD13: U48.21(O6) U71.56(CS)
PCD14: R43.2 U39.15(2A3) U40.4(I3) U71.52(INT)
PCD15: U50.16(I12) U64.21(EF)
PCD16: U50.25(O3) U64.15(R)
PCD18: U50.24(O4) U71.73(DACK)
PCD19: U50.23(O5) U71.74(DBWR)
PCD20: U44.127(EXTAL) U50.2(I1/CLK) U71.61(CLK) Y2.5(>)
PCD21: U55.13(SOUT) U72.15(T)
PCD22: U55.11(SIN) U72.3(R)
PCDSP1: U10.2(A1) U25.6(Q3)
PCDSP2: U10.3(A2) U25.9(Q4)
PCHC111: U25.12(Q5) U73.64(PE6/AN6)
PCHC112: U25.15(Q6) U73.66(PE7/AN7)
PMS-: U1.20(~{CS1}) U4.20(~{CS1}) U7.20(~{CS1}) U11.3(I2) U11.25(O3) U12.37(~{PMS})
PMS_HIGH: U4.26(CS2) U7.26(CS2) U38.17(O10)
PMS_HIGH-: U23.19(G) U28.19(G) U38.20(O7)
PMS_LOW: U1.26(CS2) U38.18(O9)
PMS_LOW-: U18.19(G) U38.21(O6)
PU1: P1.3 U73.18(~{XIRQ})
PU3: R59.2 U73.3(MODA/~{LIR})
PU4: R58.2 U73.2(MODB/VSTBY)
R/W: U73.5(R/~{W}) U74.12(I10)
R_IR_SEEN: P6.26 U73.59(PE0/AN0)
R_RX_LATCH-: P6.10 U75.15(Y0)
R_SPI_CLK: P6.18 U74.26(O2)
R_TX_LATCH-: P6.12 U75.14(Y1)
RESET_DSP-: S1.1 U12.20(~{RESET}) U20.2(Q1)
RESET_HC11-: C34.1 S2.2 U19.19(G) U24.19(G) U25.2(Q1) U29.19(G) U73.17(~{RESET}) U78.14(DO2) U79.1(~{RESET})
RFS1: U12.54(RFS1/~{IRQ0}) U74.18(O9)
ROW/COL-: P6.32 U9.11(Y4)
SPI_CLOCK: U73.32(PD4/SCK) U74.2(I1/CLK)
SPI_DSP-: U73.42(PA0/IC3) U74.3(I2)
SW1: P7.1 U80.18(B1)
SW2: P7.3 U80.17(B2)
SW3: P7.5 U80.16(B3)
SW4: P7.7 U80.15(B4)
SW5: P7.9 U80.14(B5)
SWITCHES-: U75.7(Y7) U80.19(G)
TC: P5.86(C22) P8.54(B27_TC)
TFS1: U12.53(TFS1/~{IRQ1}) U74.19(O8)
V+12: C29.1 C133.1 C134.1 C135.1 C136.1 P3.18(+12V) R41.2 R44.2
V-12: C129.1 C130.1 C131.2 C132.2 P3.14(-12V)
WE: U41.13(WE) U42.13(WE) U44.46(WR) U46.13(WE) U47.13(WE) U50.13(I11) U51.13(WE) U52.13(WE)
XA17: U35.18(Q2) U36.3(I2)
XA18: U35.17(Q3) U36.4(I3)
XA19: U35.16(Q4) U36.5(I4)
XA20: U35.15(Q5) U36.6(I5)
XA21: U35.14(Q6) U36.7(I6)
XA22: U35.13(Q7) U36.9(I7)
XA23: U35.12(Q8) U36.10(I8)
XD0: U3.9(Q0) U6.6(D0) U13.10(IN4) U18.2(A1) U19.2(A1) U20.3(D1) U21.9(Q0) U23.2(A1) U27.18(B1) U30.18(B1) U33.6(D0)
XD1: U3.10(Q1) U6.5(D1) U15.10(IN4) U18.3(A2) U19.3(A2) U20.4(D2) U21.10(Q1) U23.3(A2) U27.17(B2) U30.17(B2) U33.5(D1)
XD2: U3.11(Q2) U6.4(D2) U16.10(IN4) U18.4(A3) U19.4(A3) U20.7(D3) U21.11(Q2) U23.4(A3) U27.16(B3) U30.16(B3) U33.4(D2)
XD3: U3.12(Q3) U6.3(D3) U18.5(A4) U19.5(A4) U20.8(D4) U21.12(Q3) U23.5(A4) U27.15(B4) U30.15(B4) U33.3(D3)
XD4: U3.16(Q4) U6.27(D4) U18.6(A5) U19.6(A5) U20.13(D5) U21.16(Q4) U23.6(A5) U27.14(B5) U30.14(B5) U33.27(D4)
XD5: U3.17(Q5) U6.26(D5) U18.7(A6) U19.7(A6) U20.14(D6) U21.17(Q5) U23.7(A6) U27.13(B6) U30.13(B6) U33.26(D5)
XD6: U3.18(Q6) U6.25(D6) U18.8(A7) U19.8(A7) U20.17(D7) U21.18(Q6) U23.8(A7) U27.12(B7) U30.12(B7) U33.25(D6)
XD7: U3.19(Q7) U6.24(D7) U18.9(A8) U19.9(A8) U20.18(D8) U21.19(Q7) U23.9(A8) U27.11(B8) U30.11(B8) U33.24(D7)
XD8: U25.3(D1) U26.9(Q0) U28.2(A1) U31.18(B1) U32.18(B1) U37.6(D0)
XD9: U25.4(D2) U26.10(Q1) U28.3(A2) U31.17(B2) U32.17(B2) U37.5(D1)
XD10: U25.7(D3) U26.11(Q2) U28.4(A3) U31.16(B3) U32.16(B3) U37.4(D2)
XD11: U25.8(D4) U26.12(Q3) U28.5(A4) U31.15(B4) U32.15(B4) U37.3(D3)
XD12: U25.13(D5) U26.16(Q4) U28.6(A5) U31.14(B5) U32.14(B5) U37.27(D4)
XD13: U25.14(D6) U26.17(Q5) U28.7(A6) U31.13(B6) U32.13(B6) U37.26(D5)
XD14: U25.17(D7) U26.18(Q6) U28.8(A7) U31.12(B7) U32.12(B7) U37.25(D6)
XD15: U25.18(D8) U26.19(Q7) U28.9(A8) U31.11(B8) U32.11(B8) U37.24(D7)
N00091: D2.1 U20.19(Q8)
N00165: R23.1 U34.24(O4)
N00167: R24.1 U34.23(O5)
N00169: R25.1 U34.21(O6)
N00172: R26.1 U34.20(O7)
N01550: R57.2 U73.68(VRH)
N01559: U73.4(E) U74.11(I9)
N01564: U74.17(O10) U75.5(G2B)
N01565: U73.20(PG7/~{CSPRG}) U74.13(I11)
N01566: U73.21(PG6/CSGEN) U74.16(I12)
N01569: C30.2 R60.1 U73.7(XTAL) Y4.1
N01580: C31.2 R60.2 U73.6(EXTAL) Y4.2
N01582: TP4.1 U73.8(4XOUT)
N01654: P9.4 U78.5(RX1)
N01659: P9.7 U78.7(RX2)
N01660: P9.2 U78.10(TX3)
N01662: P9.3 U78.9(RX3)
N01672: C32.1 U78.1(C2+)
N01673: C33.1 U78.20(C1+)
N01680: C32.2 U78.3(C2-)
N01681: C33.2 U78.18(C1-)
N01686: C35.2 U78.4(VSS)
N01687: C36.1 U78.17(VDD)
N03350: E6.2 U63.4(EN) U66.2(RE) U66.3(DE) U70.2(RE) U70.3(DE) U72.4(EN)
N03353: U58.15(QA) U65.3(I2)
N03354: U58.14(SER) U63.3(R)
N03363: U60.12(QC) U65.4(I3)
N03368: U60.13(QB) U65.5(I4)
N03374: U60.14(QA) U65.6(I5)
N03375: U59.3(I2) U68.15(RCO)
N03378: U61.13(O0) U62.11(A)
N03379: P4.9 U63.14(Y)
N03383: U58.12(RCLK) U65.27(O1) U69.11(CLK)
N03387: U61.14(O1) U62.12(B)
N03388: U62.9(QH) U63.15(T)
N03393: U57.24(D7) U58.13(G) U64.24(D7) U65.26(O2)
N03396: U61.15(O2) U62.13(C)
N03397: P4.22 U63.13(Z)
N03398: P4.14 U63.6(A)
N03405: U61.17(O3) U62.14(D)
N03406: P4.2 U63.7(B)
N03411: U61.18(O4) U62.3(E)
N03412: P4.3 U63.2(A)
N03417: U61.19(O5) U62.4(F)
N03421: U57.1(W) U65.25(O3)
N03425: U61.20(O6) U62.5(G)
N03426: P4.16 U63.1(B)
N03432: U61.21(O7) U62.6(H)
N03439: P4.17 U63.10(Y)
N03443: P4.5 U63.11(Z)
N03450: P4.6 U66.6(A])
N03454: P4.19 U66.7(B)
N03466: P4.20 U70.6(A])
N03472: P4.8 U70.7(B)
N03500: U64.1(W) U65.19(O8)
N03510: U62.1(SH/~{LD}) U65.18(O9)
N03516: P4.23 U72.2(A)
N03519: U65.17(O10) U69.1(OC)
N03527: P4.11 U72.1(B)
N03539: P4.12 U72.14(Y)
N03546: P4.25 U72.13(Z)
N03552: JP4.2 R40.2 U63.12(EN)
N03581: Q2.2 R42.1 R44.1
N03584: JP5.2 U71.12(SDI0) U71.23(SDO0)
N03588: JP5.4 U71.13(SDI1) U71.24(SDO1)
N03590: D3.1 Q2.3 R47.2
N03593: JP5.6 U71.14(SDI2) U71.25(SDO2)
N03597: JP5.8 U71.15(SDI3) U71.26(SDO3)
N03601: Q3.2 R46.1
N03603: JP5.10 U71.16(SDI4) U71.28(SDO4)
N03609: JP5.12 U71.17(SDI5) U71.29(SDO5)
N03612: JP5.14 U71.18(SDI6) U71.30(SDO6)
N03613: JP5.16 U71.19(SDI7) U71.31(SDO7)
N03615: Q5.3 R48.2 R49.2
N03616: Q4.2 R49.1 R51.2
N03619: JP5.18 U71.20(SDIP) U71.32(SDOP)
N03624: Q5.2 R50.2
N03663: R53.2 U71.1(DBP0)
N03664: R52.2 U71.11(DBP1)
N03667: R55.1 R56.2 U71.72(DREQ)
N03673: Q6.2 R55.2
N05398: U39.11(2A1) U40.6(I5) U55.33(INTRPT)
N05400: R29.1 U39.13(2A2) U40.5(I4) U44.10(HREQ) U49.16(I12)
N05420: U40.2(I1/CLK) U49.19(O8)
N05437: U39.19(2G) U40.7(I6) U48.18(O9)
N05442: U40.9(I7) U48.17(O10) U49.13(I11)
N05446: U40.10(I8) U49.27(O1)
N05454: P3.19(I/ORDY) U40.17(O10)
N05459: U43.9(O) U45.1(I1)
N05492: U48.19(O8) U55.16(/CS2)
N05499: U48.26(O2) U48.27(O1) U53.1(DIR) U53.19(G)
N05501: U48.16(I12) U49.26(O2)
N05502: U44.8(HEN) U49.18(O9)
N05509: U44.6(HACK) U49.17(O10)
N05552: U44.52(PS) U45.7(I7) U50.9(I7)
N05553: U45.13(O7) U50.27(O1)
N05557: U44.49(DS) U45.8(I8) U50.10(I8)
N05558: U44.45(BR/WT) U45.12(O8) U50.7(I6)
N05562: U44.48(X/Y) U45.9(I9) U50.11(I9)
N05566: U44.43(BG/BS) U45.11(I10)
N05576: U44.47(RD) U50.12(I10)
N05592: U48.10(I8) U49.10(I8) U54.17(O3)
N05596: U48.9(I7) U49.9(I7) U54.19(O1)
N05614: U48.2(I1/CLK) U49.2(I1/CLK) U56.18(B1)
N05621: P3.35(SA13) U48.5(I4) U49.3(I2)
N05627: P3.33(SA14) U48.4(I3) U49.4(I3)
N05632: P3.31(SA15) U48.3(I2) U49.5(I4)
N05638: U48.12(I10) U54.15(O5)
N05642: U48.11(I9) U54.16(O4)
N05644: R34.1 U50.17(O10)
N05658: P3.21(AEN) U54.18(O2)
N05664: U49.12(I10) U54.12(O8)
N05695: JP1.1 JP3.1 Q1.3
N05699: U55.10(RCLK) U55.17(/BAUD)
N05704: JP2.2 U55.40(/CTS)
N05705: E5.2 R33.2 U54.11(I10)
N05708: JP2.3 U55.37(/DTR)
N05709: JP2.4 U55.41(/DSR)
N05710: E4.2 R32.2 U54.9(I9)
N05712: JP2.5 U55.36(/RTS)
N05713: JP2.6 U55.42(/DCD)
N05714: E3.2 R31.2 U54.8(I8)
N05717: JP2.7 U55.38(/OUT1)
N05718: JP2.8 U55.43(/RI)
N05721: E2.2 R30.2 U54.7(I7)
N05724: JP2.9 U55.35(/OUT2)
N05725: P3.53(SA4) U54.1(I1)
N05728: P3.51(SA5) U54.2(I2)
N05732: Q1.2 R34.2
N05734: P3.49(SA6) U54.3(I3)
N05735: P3.26(I/OW) R36.1
N05740: P3.47(SA7) U54.4(I4)
N05741: P3.28(I/OR) R35.1
N05746: P3.45(SA8) U54.5(I5)
N05747: P3.40(CLK) R37.1
N05757: C27.1 R36.2 U56.4(A3)
N05759: C24.1 R38.1 U55.18(XTAL1) Y3.2
N05761: C26.1 R35.2 U56.3(A2)
N05762: C25.1 R37.2 U56.2(A1)
N05767: R39.1 U55.19(XTAL2)
N05768: C28.1 R38.2 R39.2 Y3.1
N05812: P3.3(SD7) U53.9(A8)
N05816: P3.5(SD6) U53.8(A7)
N05820: P3.7(SD5) U53.7(A6)
N05823: P3.9(SD4) U53.6(A5)
N05827: P3.11(SD3) U53.5(A4)
N05829: P3.13(SD2) U53.4(A3)
N05834: P3.15(SD1) U53.3(A2)
N05836: P3.17(SD0) U53.2(A1)
N05875: P3.43(SA9) U54.6(I6)
N08018: P2.3 U12.51(SCLK0)
N08019: P2.4 U12.48(RFS0)
N08020: P2.5 U12.47(TFS0)
N08021: P2.6 U12.46(DT0)
N08022: P2.7 U12.50(DR0)
N08026: C3.2 U12.42(CLKIN) Y1.2
N08030: C4.2 U12.41(XTAL) Y1.1
N08078: R5.1 U13.20(OUT) U14.3(IN+)
N08080: R4.1 R9.2 U14.1(OUT)
N08081: C7.1 L1.1 R4.2 R7.1
N08082: C8.1 L1.2 L2.1
N08083: C5.2 C9.1 L2.2 R8.1
N08086: C6.1 U13.19(BYP)
N08087: R6.1 R9.1 U14.2(IN-)
N08106: R11.1 U14.5(IN+) U15.20(OUT)
N08108: R10.1 R15.2 U14.7(OUT)
N08109: C12.1 L3.1 R10.2 R13.1
N08110: C13.1 L3.2 L4.1
N08111: C10.2 C14.1 L4.2 R14.1
N08114: C11.1 U15.19(BYP)
N08115: R12.1 R15.1 U14.6(IN-)
N08134: R17.1 U14.10(IN+) U16.20(OUT)
N08136: R16.1 R21.2 U14.8(OUT)
N08137: C17.1 L5.1 R16.2 R19.1
N08138: C18.1 L5.2 L6.1
N08139: C15.2 C19.1 L6.2 R20.1
N08142: C16.1 U16.19(BYP)
N08143: R18.1 R21.1 U14.9(IN-)
N09208: R1.1 U9.15(Y0)
N09210: D1.1 U8.19(Q8)
N09211: R2.1 U9.14(Y1)
N09217: TP1.1 U9.7(Y7)
N1378627: R61.2 U77.9(VZ)
N1379788: Q3.3 R42.2
N1379796: Q2.1 R41.1
N1381751: D2.2 R22.1
N1382931: D1.2 R3.1

Not connected (* = marked no-connect by the designer): C5 1; C10 1; C15 1; E1 1 2; J1 1(CENTER); J2 1(CENTER); J3 1(CENTER); JP2 10; P1 10 12; P2 2; P3 1(I/OCK)* 4(RESET)* 8(IRQ2)* 12(DRQ2)* 16(SRDY)* 20(GND1) 22(SMEMW)* 23(SA19)* 24(SMEMR)* 25(SA18)* 27(SA17)* 29(SA16)* 30(DACK3)* 32(DRQ3)* 34(DACK1)* 36(DRQ1)* 37(SA12)* 38(RFSH)* 39(SA11)* 41(SA10)* 42(IRQ7) 44(IRQ6)* 46(IRQ5) 48(IRQ4) 50(IRQ3) 52(DACK2)* 54(T/C)* 56(BALE)* 60(OSC)*; P6 36 38 40 42 44 46 48 49 50; P7 11 13 14; P8 1(~{IOCHCHK}_A01)* 10(B05_-5V)* 12(B06_DRQ2)* 16(B08_~{SRDY})* 22(B11_~{SMEMW})* 24(B12_~{SMEMR})* 30(B15_~{DACK3})* 32(B16_DRQ3)* 34(B17_~{DACK1})* 36(B18_DRQ1)* 38(B19_~{REFRESH})* 40(B20_SYSCLK)* 42(B21_IRQ7)* 44(B22_IRQ6)* 46(B23_IRQ5)* 48(B24_IRQ4)* 50(B25_IRQ3)* 52(B26_~{DACK}2)* 60(B30_OSC)* 63(~{SBHE}_C01)* 70(D04_IRQ11)* 72(D05_IRQ12)* 74(D06_IRQ15)* 76(D07_IRQ14)* 78(D08_~{DACK0})* 80(D09_DRQ0)* 82(D10_~{DACK}5)* 84(D11_DRQ5)* 86(D12_~{DACK}6)* 88(D13_DRQ6)* 96(D17_~{MASTER})*; P9 1 6 8 9 10; U3 2(D8)* 13(Q8)* 20(~{XO}/~{HF})*; U6 2(D8)* 13(Q8)* 20(~{XO}/~{HF})*; U8 12(Q5)* 15(Q6)* 16(Q7)*; U11 17(O10)* 20(O7)* 27(O1)*; U20 12(Q5)*; U21 2(D8)* 13(Q8)* 20(~{XO}/~{HF})*; U25 16(Q7)* 19(Q8)*; U26 2(D8)* 8(~{FF})* 13(Q8)* 20(~{XO}/~{HF})* 21(~{EF})*; U32 6(A5)* 7(A6)* 8(A7)* 9(A8)*; U33 2(D8)* 13(Q8)* 20(~{XO}/~{HF})*; U35 19(Q1)*; U37 2(D8)* 8(~{FF})* 13(Q8)* 20(~{XO}/~{HF})* 21(~{EF})*; U38 26(O2)* 27(O1)*; U39 14(1Y3)* 18(1Y1)*; U40 18(O9) 19(O8)* 20(O7)* 21(O6)* 23(O5)* 24(O4)* 25(O3)* 26(O2)*; U44 28(TXD)* 29(SCLK)* 37(SC2)* 39(STD)* 42(SRD)* 126(XTAL)*; U48 23(O5)*; U49 20(O7)* 21(O6)* 23(O5)*; U50 18(O9)* 19(O8)* 20(O7)* 21(O6)*; U54 14(O6)*; U55 26(/DDIS)* 27(CSOUT)*; U56 15(B4)*; U57 8(FULL)* 13(Q8)* 20(XO/HF)*; U58 9(QH_); U59 17(O10)* 18(O9)*; U62 7(~{QH})*; U64 8(FULL)* 13(Q8)* 20(XO/HF)*; U65 20(O7)* 21(O6)* 23(O5)* 24(O4)*; U69 19(Q7)*; U73 31(PD3/MOSI)*; U77 6(IN6)* 7(IN7)* 10(OUT7)* 11(OUT6)*; U78 6(TX1)* 8(TX2)* 13(DI2)* 15(DI1)*; U80 1(DIR)* 7(A6)* 8(A7)* 9(A8)* 11(B8)* 12(B7)* 13(B6)*

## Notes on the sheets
sheet 1
- HC11 to PC FIFO
- PC to HC11 FIFO
- 8k x 16 Data Memory
- 8k x 24 Program Memory
sheet 3
- DSP to PC FIFO
- PC to DSP FIFO
sheet 4
- I/O
- FF
- FIFO
- /WRITE
- /READ
sheet 5
- <
- <
- >
- >
- >
- >
- <
- >
